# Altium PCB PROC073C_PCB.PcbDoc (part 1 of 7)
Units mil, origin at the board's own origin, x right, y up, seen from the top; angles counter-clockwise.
Board outline 2165.35 x 2695.12 mil, 8 copper layers (Top Layer, L2_GND, L3_SIGNAL 1, L4_SIGNAL 2, L5_SIGNAL 3, L6_SIGNAL 4, L7_GND, Bottom Layer), stack 55.9 mil thick; 393 components, 319 nets, 1311 pads, 1643 vias.
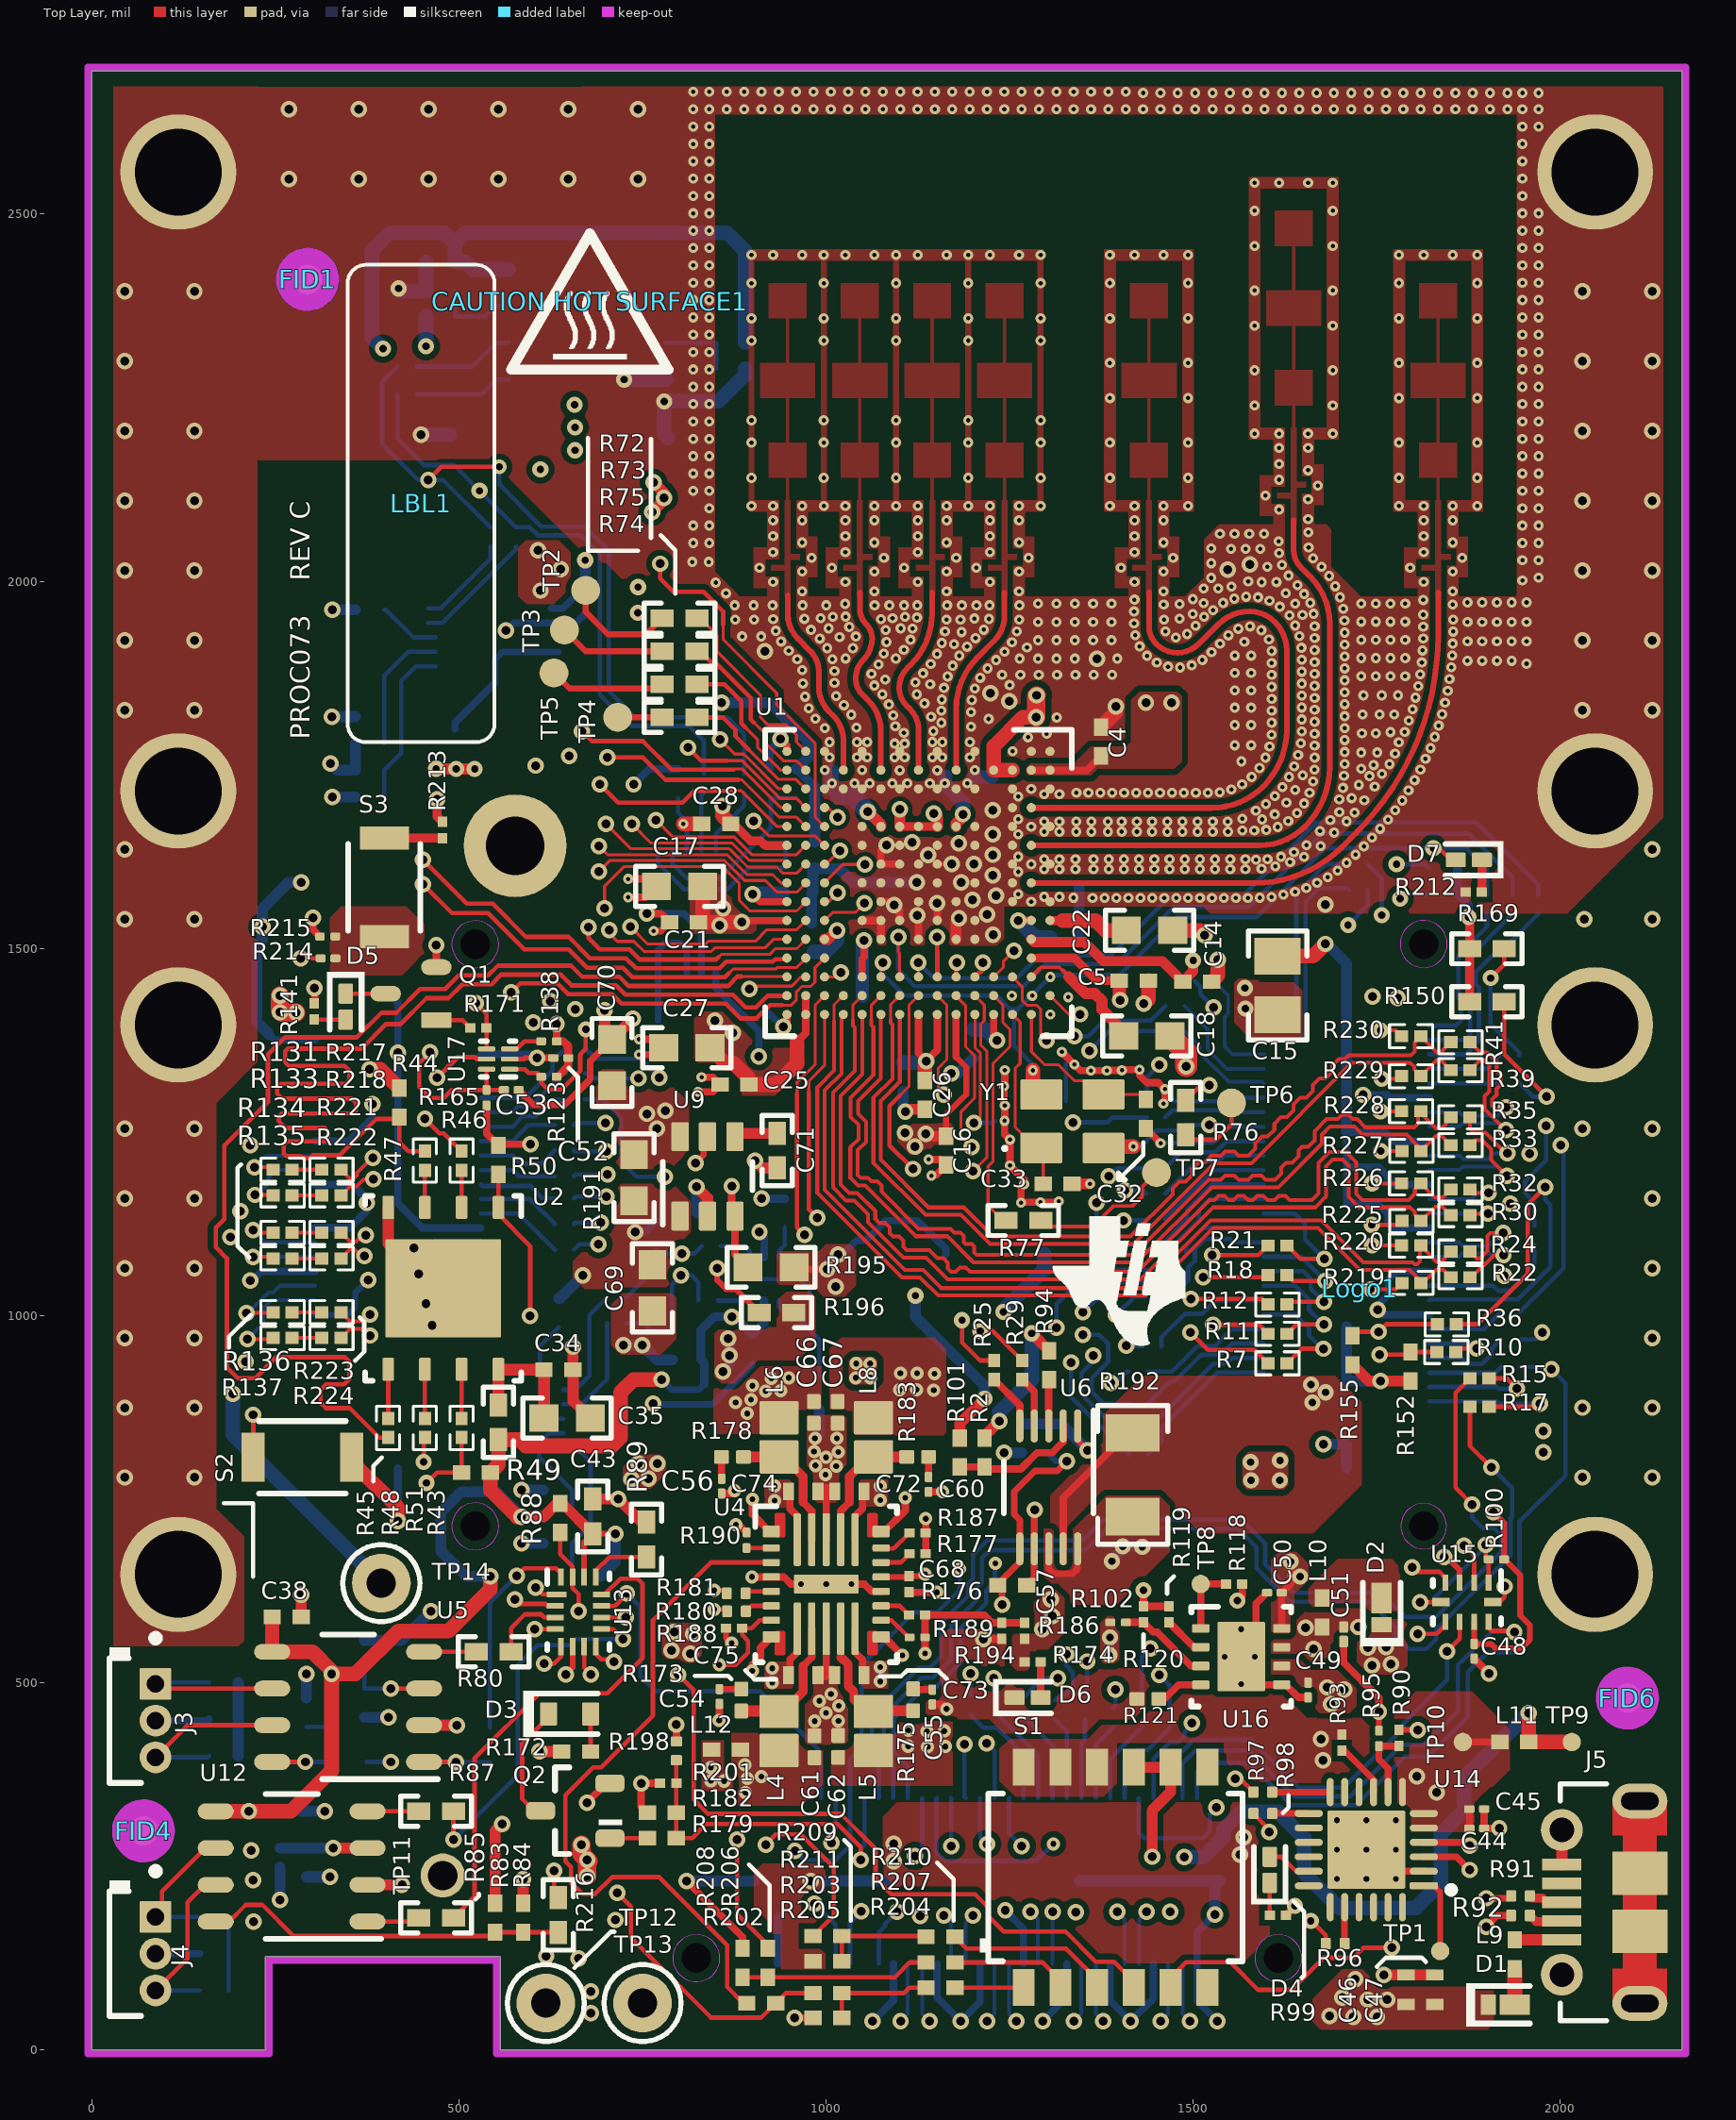
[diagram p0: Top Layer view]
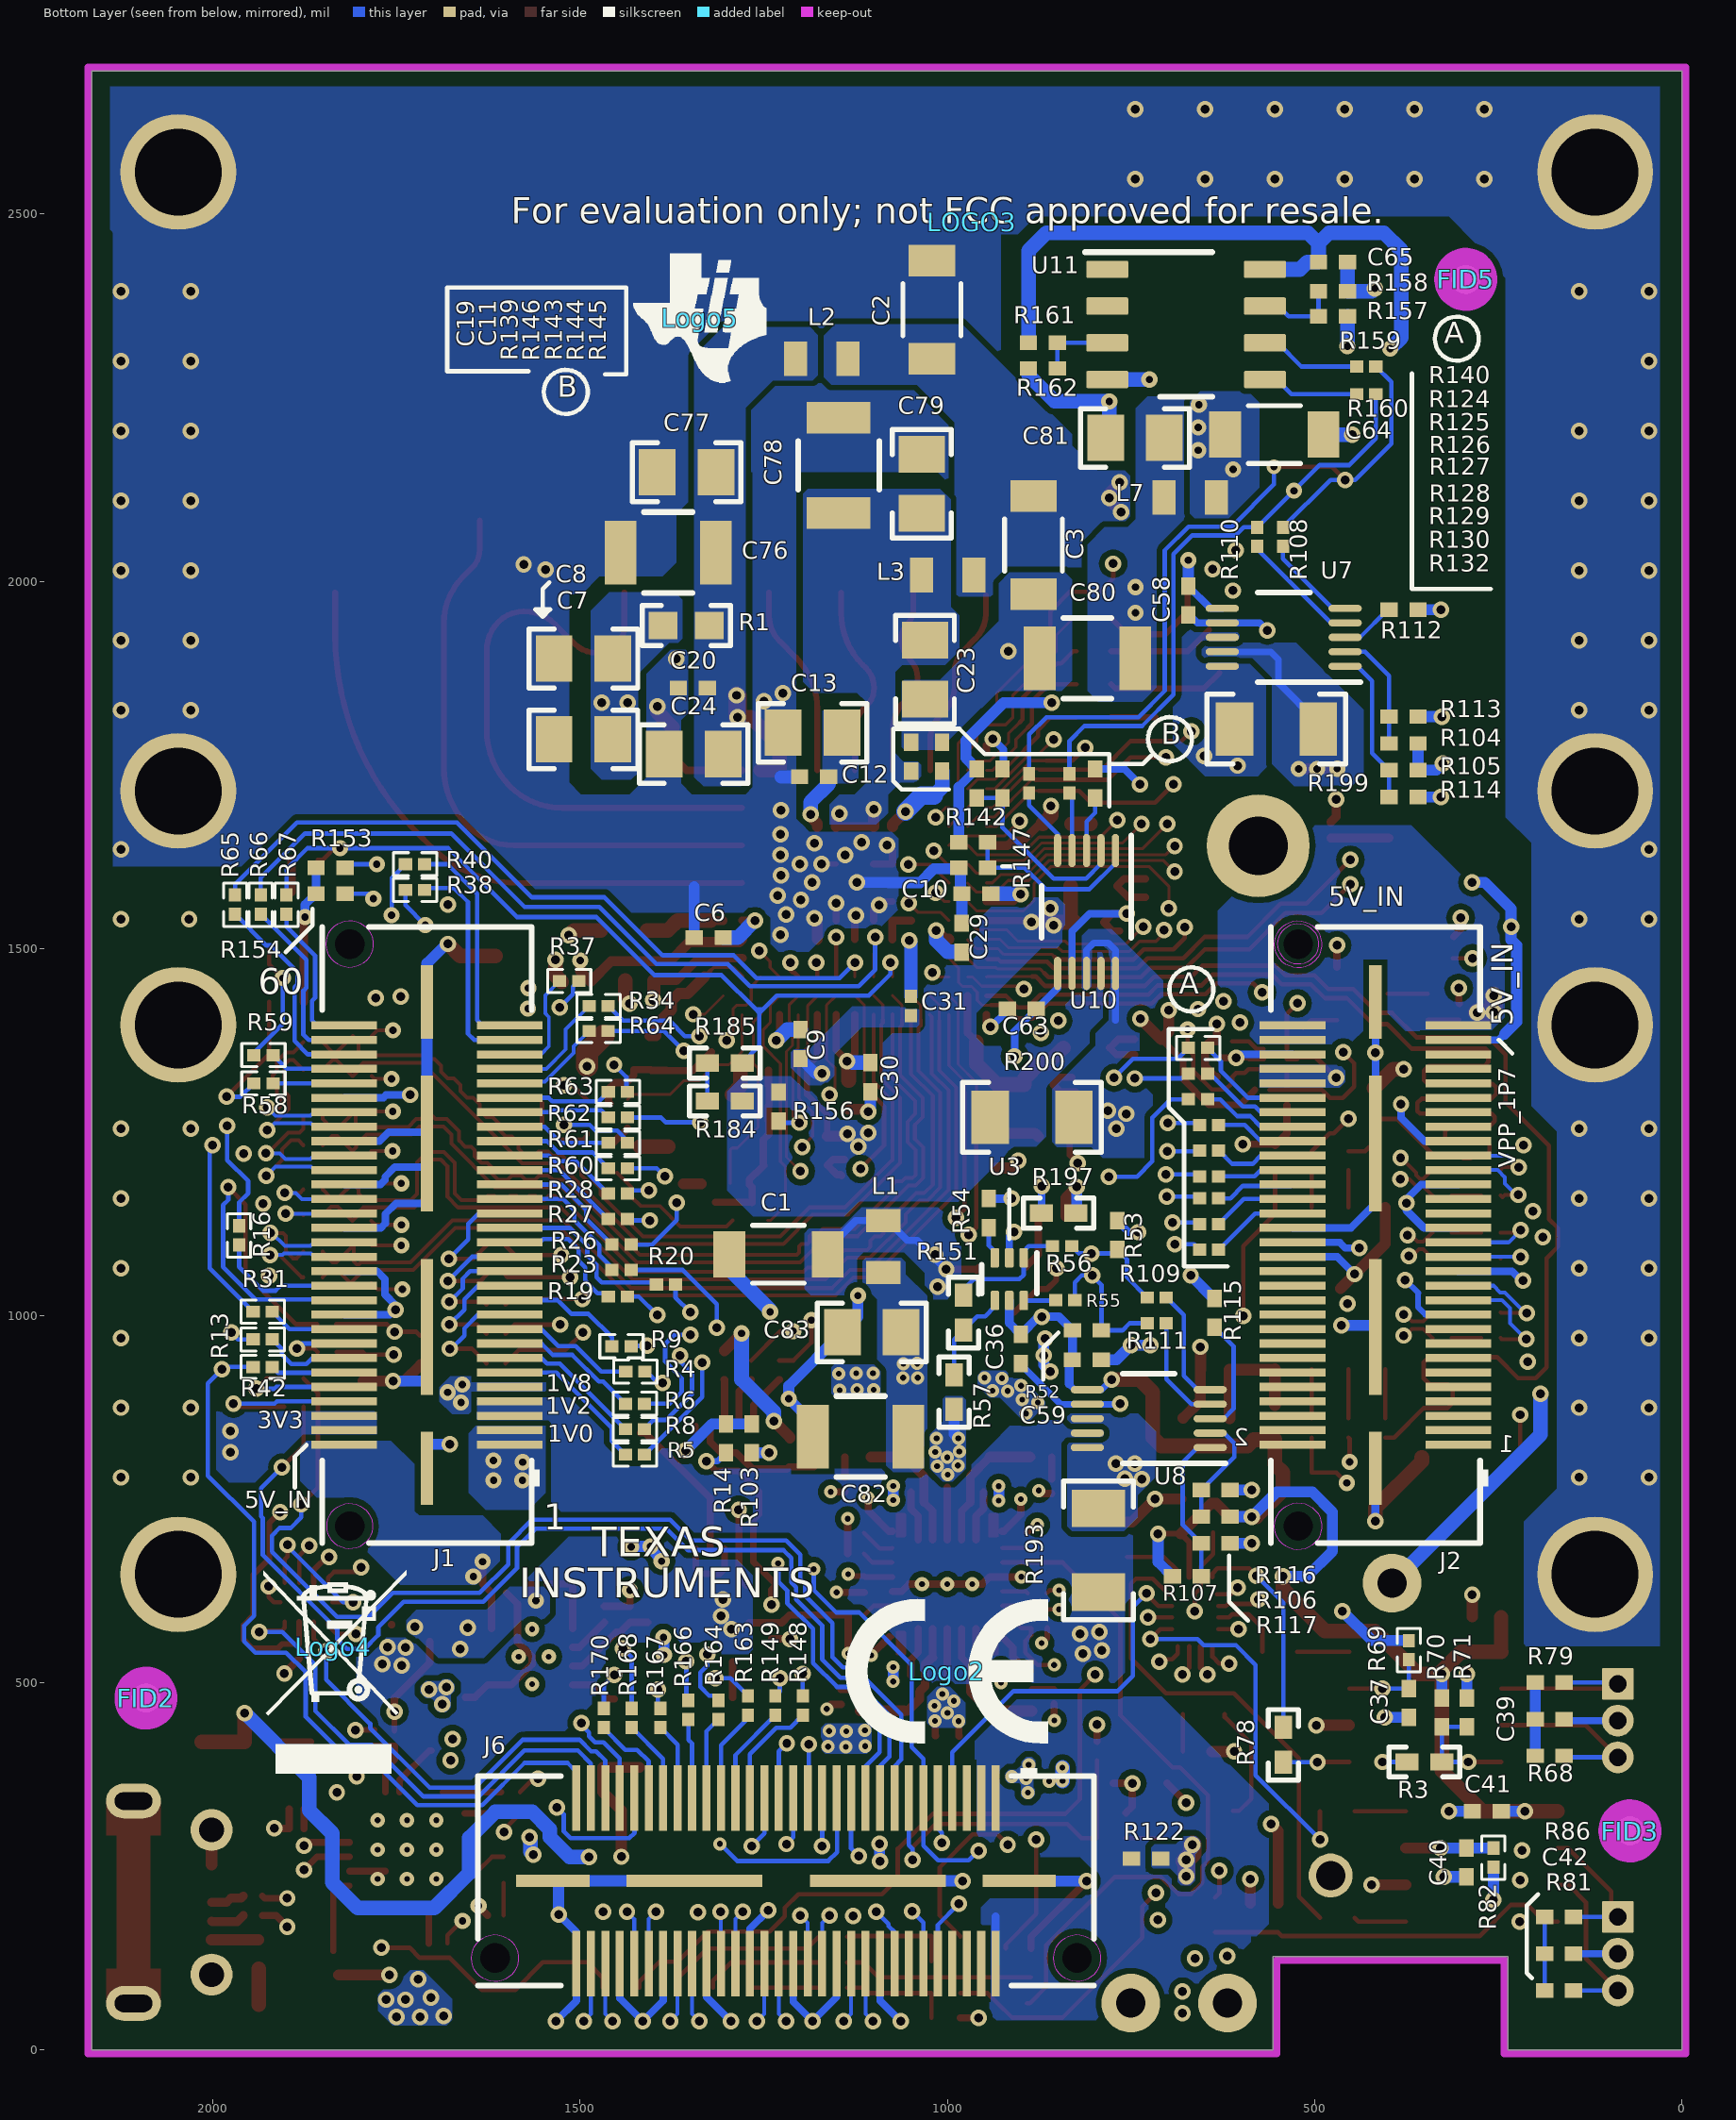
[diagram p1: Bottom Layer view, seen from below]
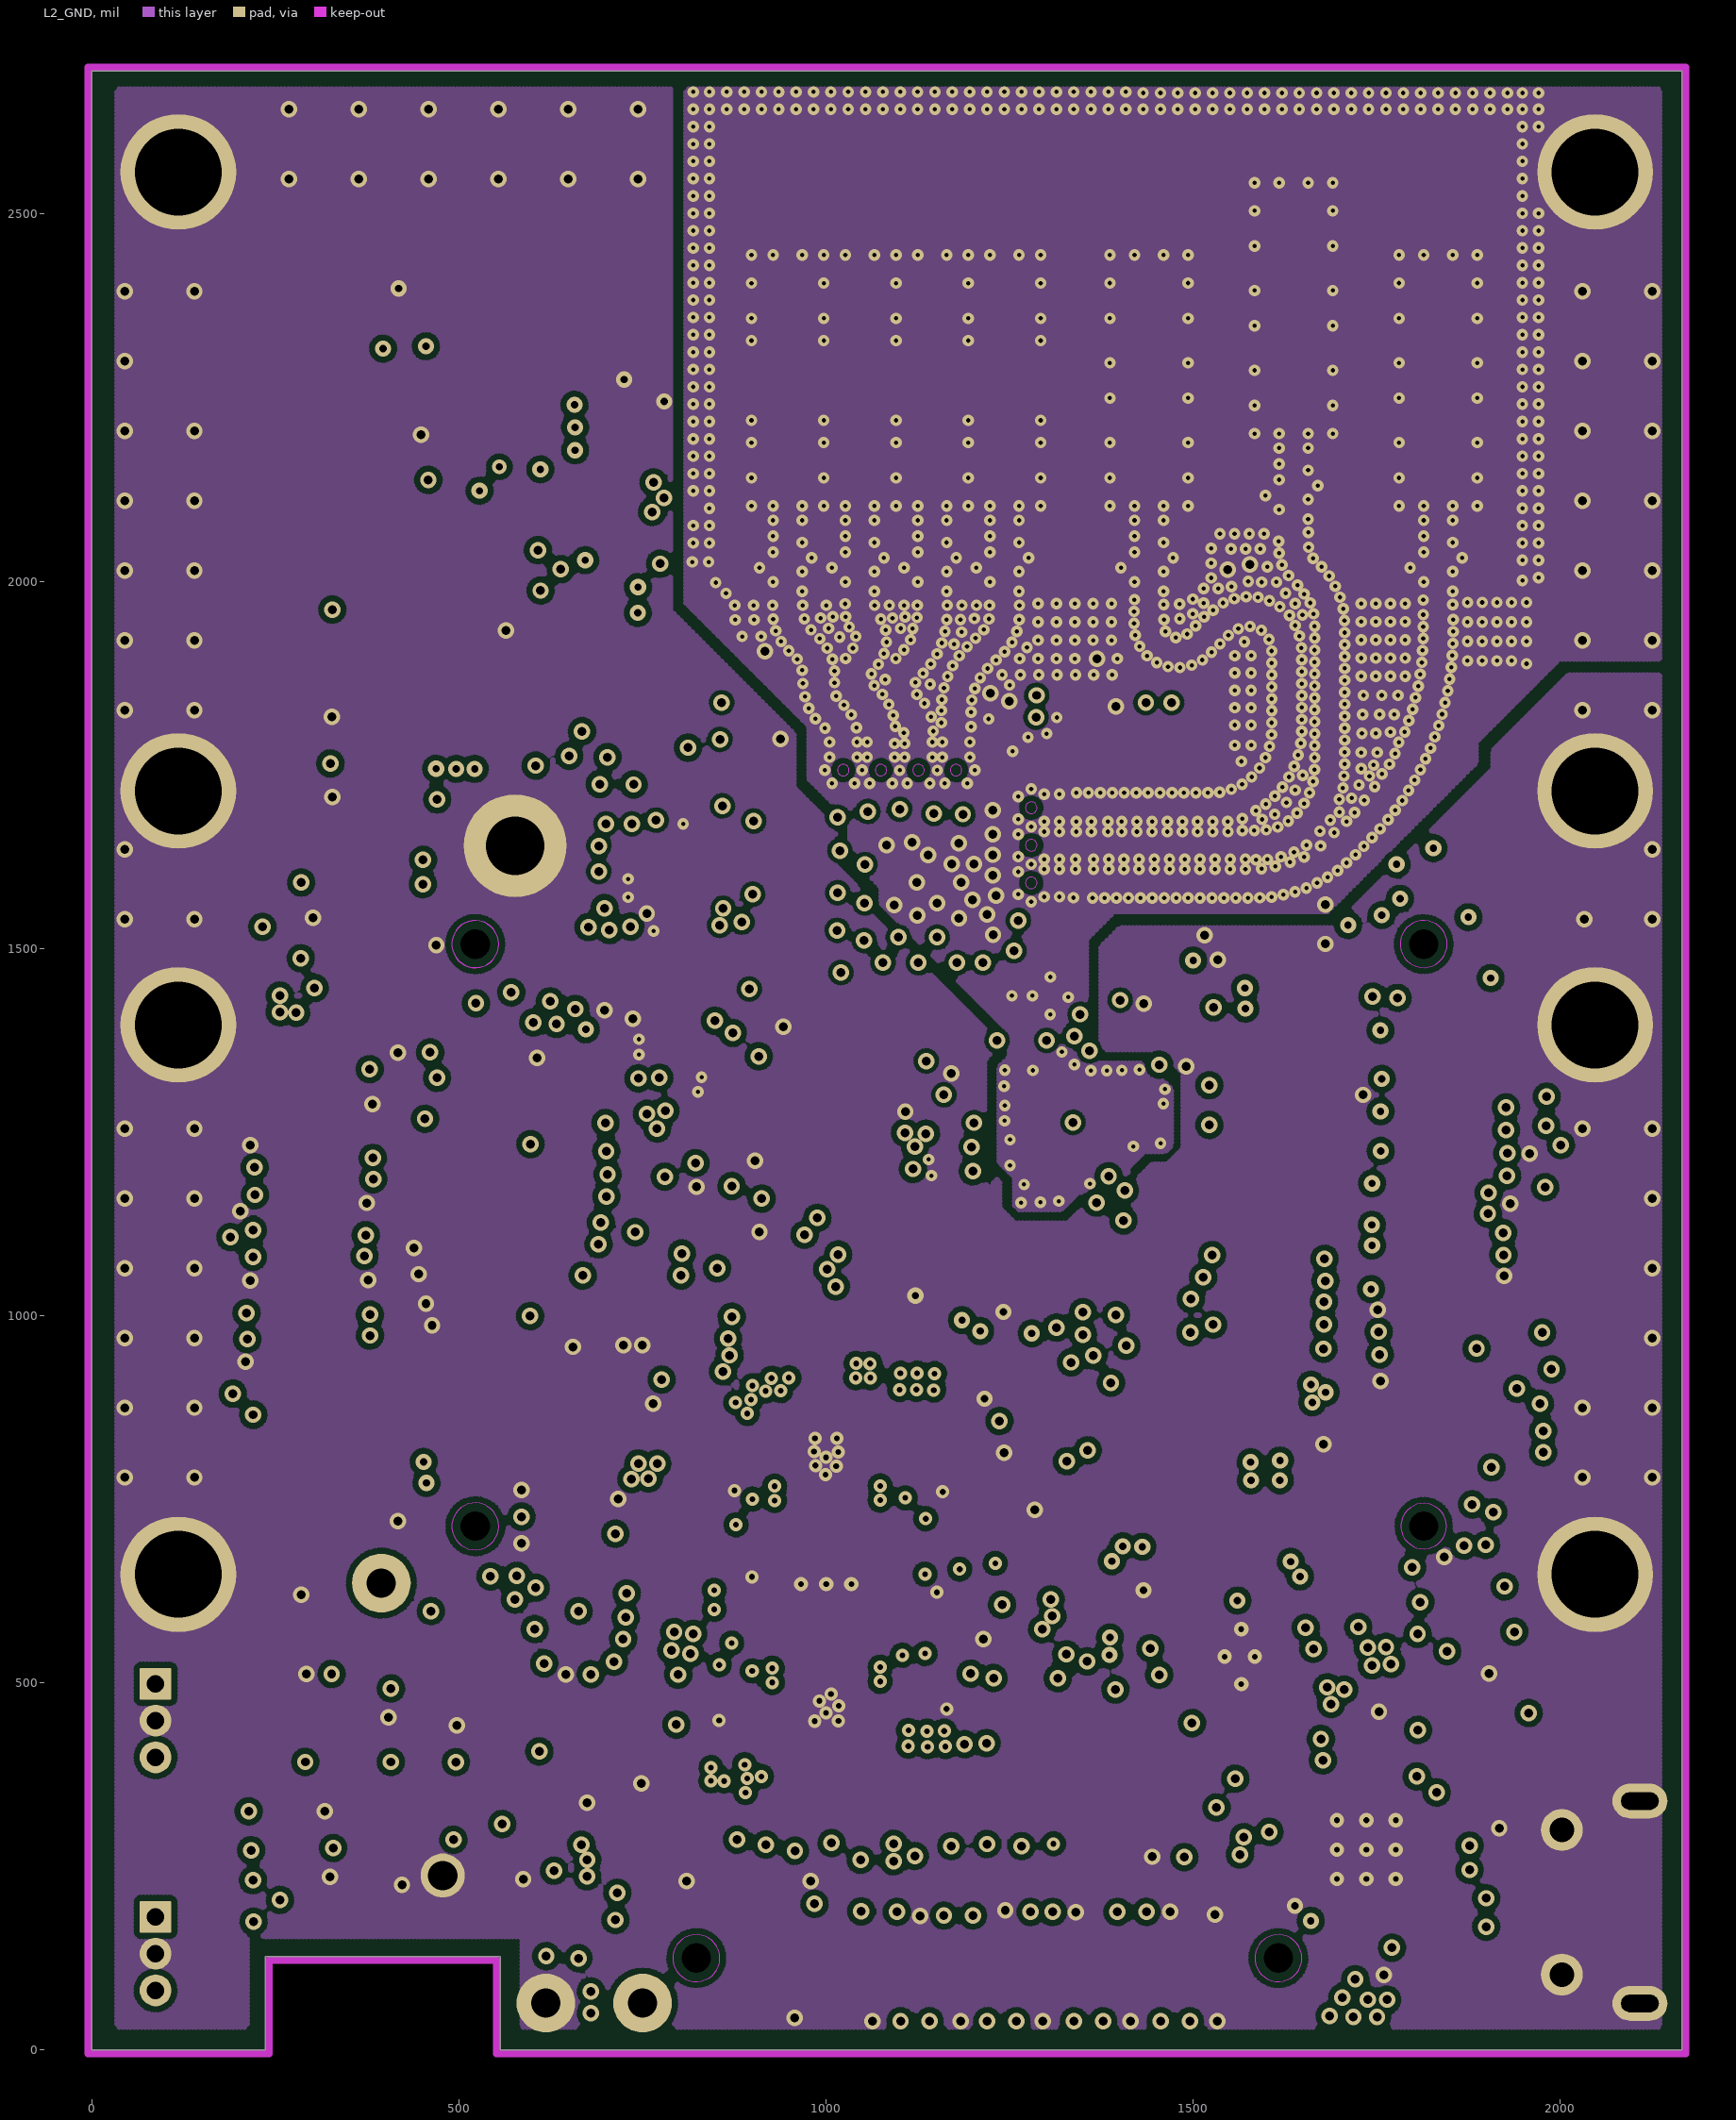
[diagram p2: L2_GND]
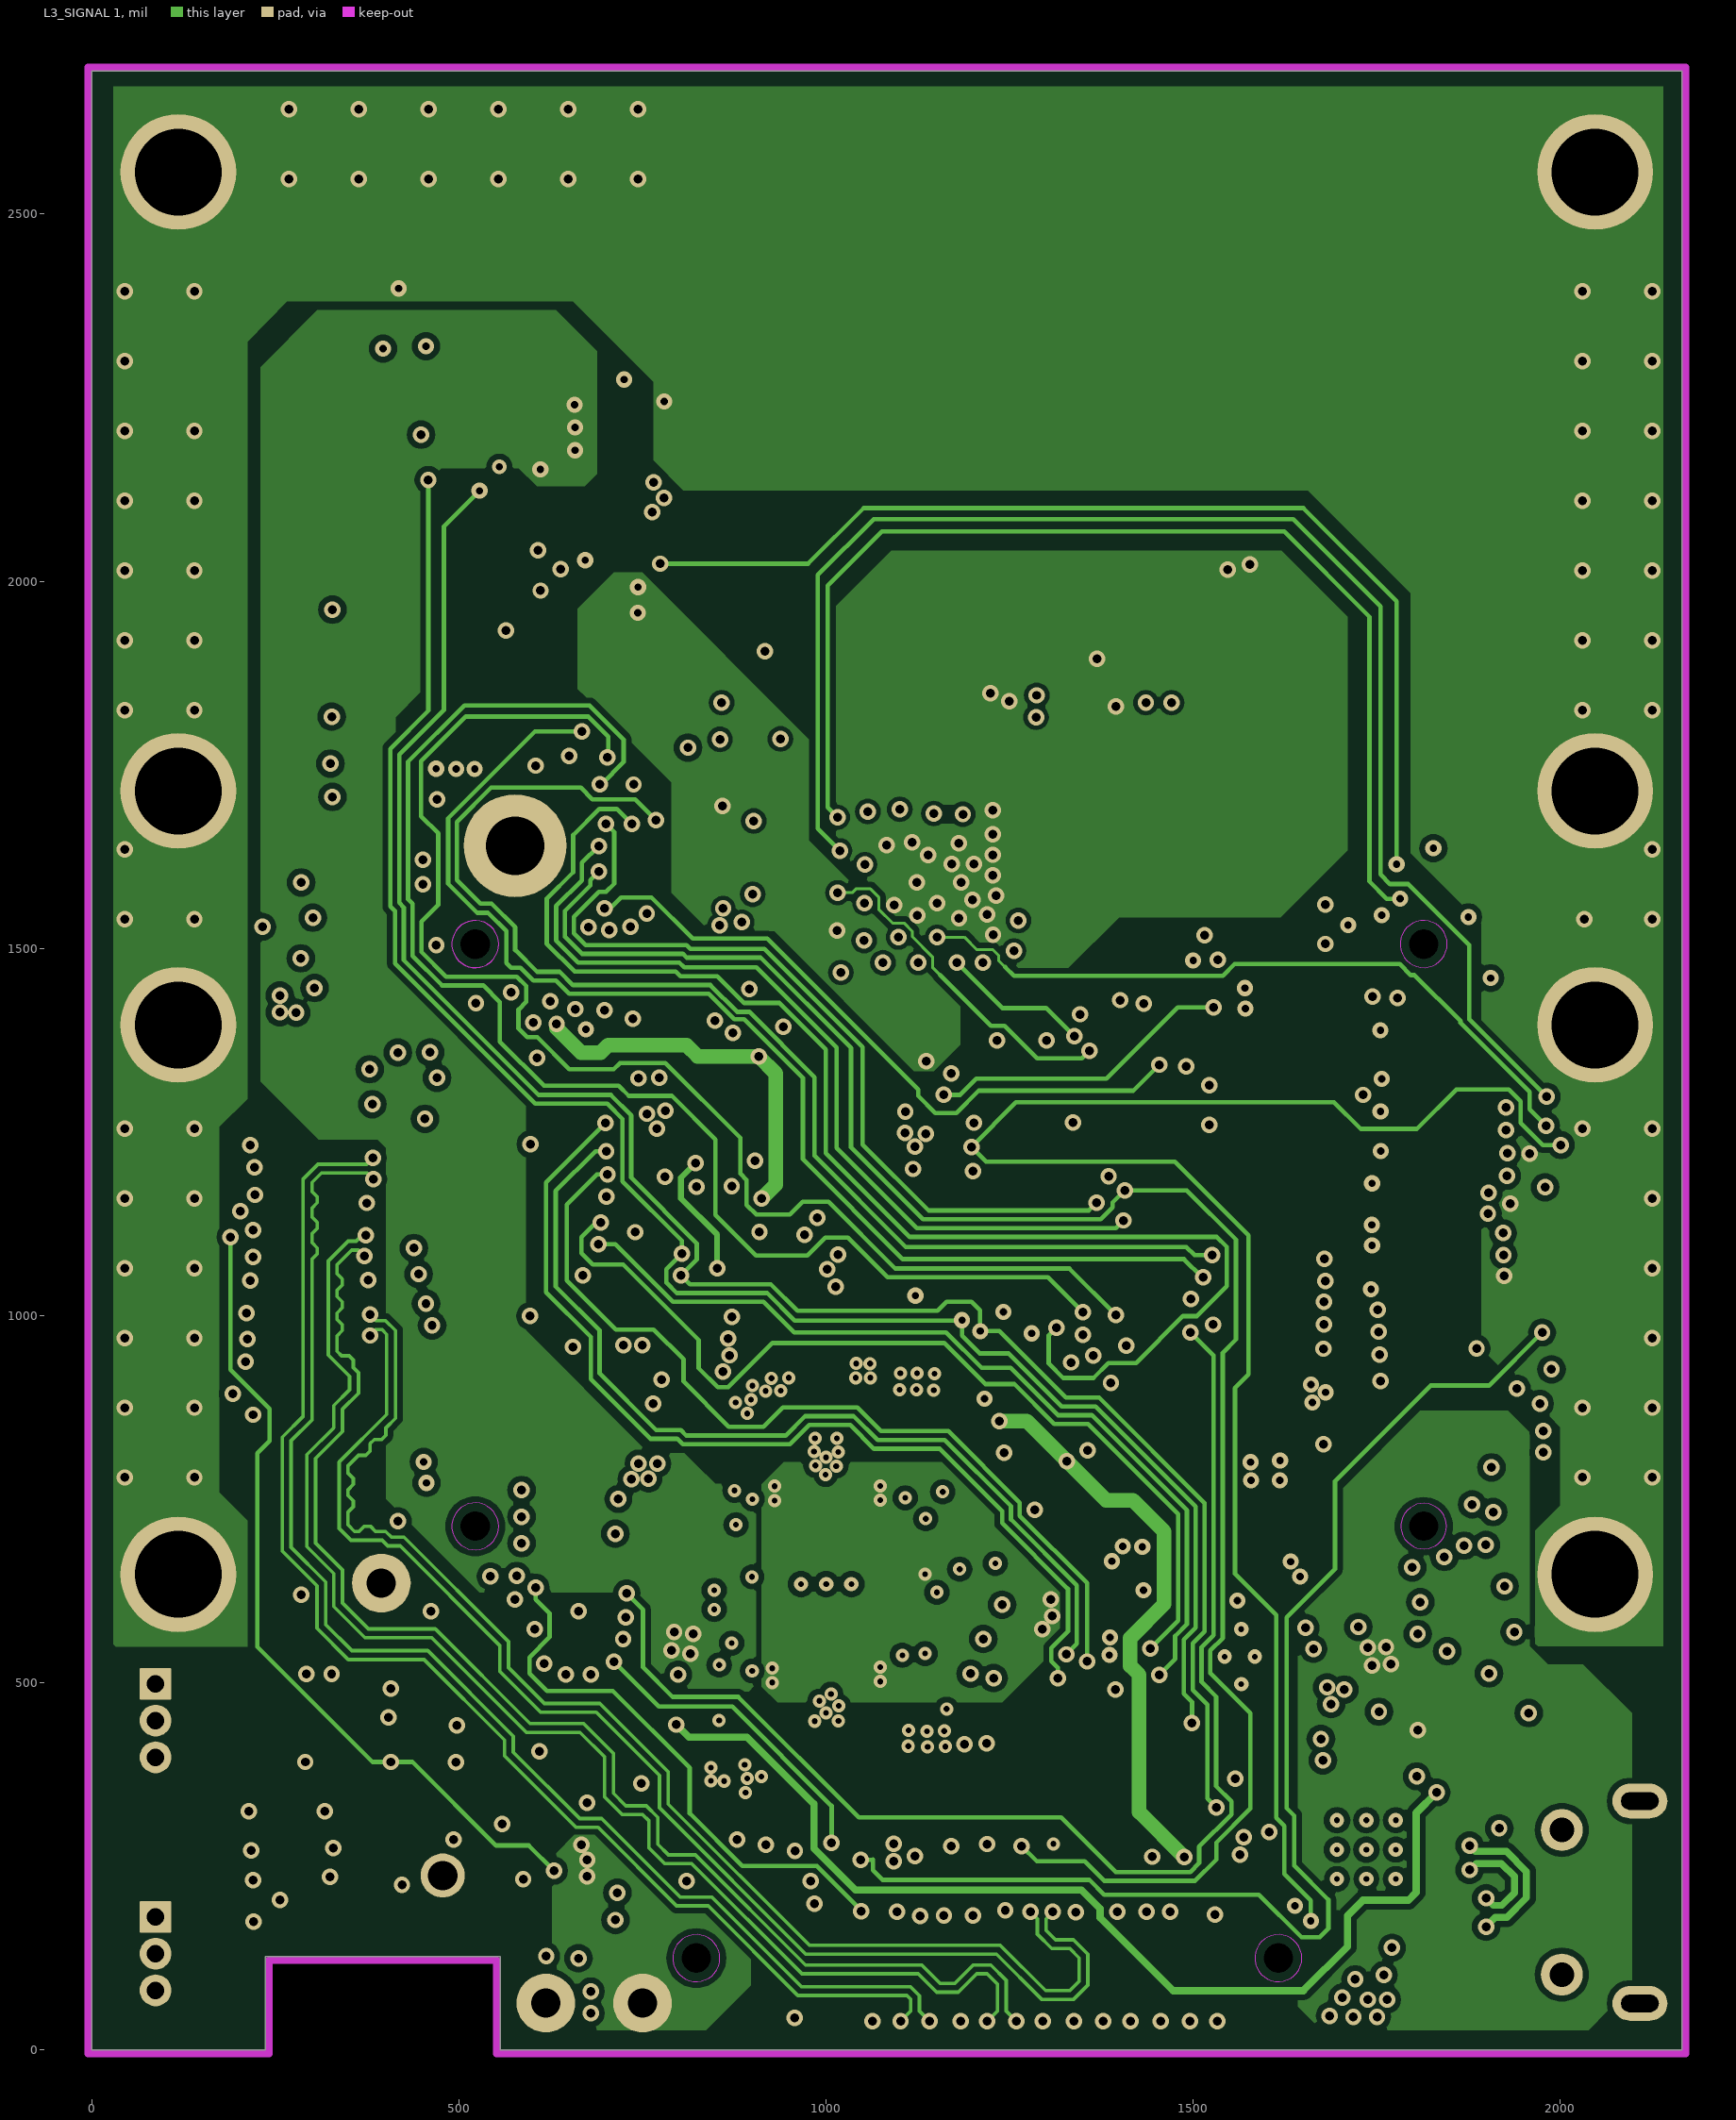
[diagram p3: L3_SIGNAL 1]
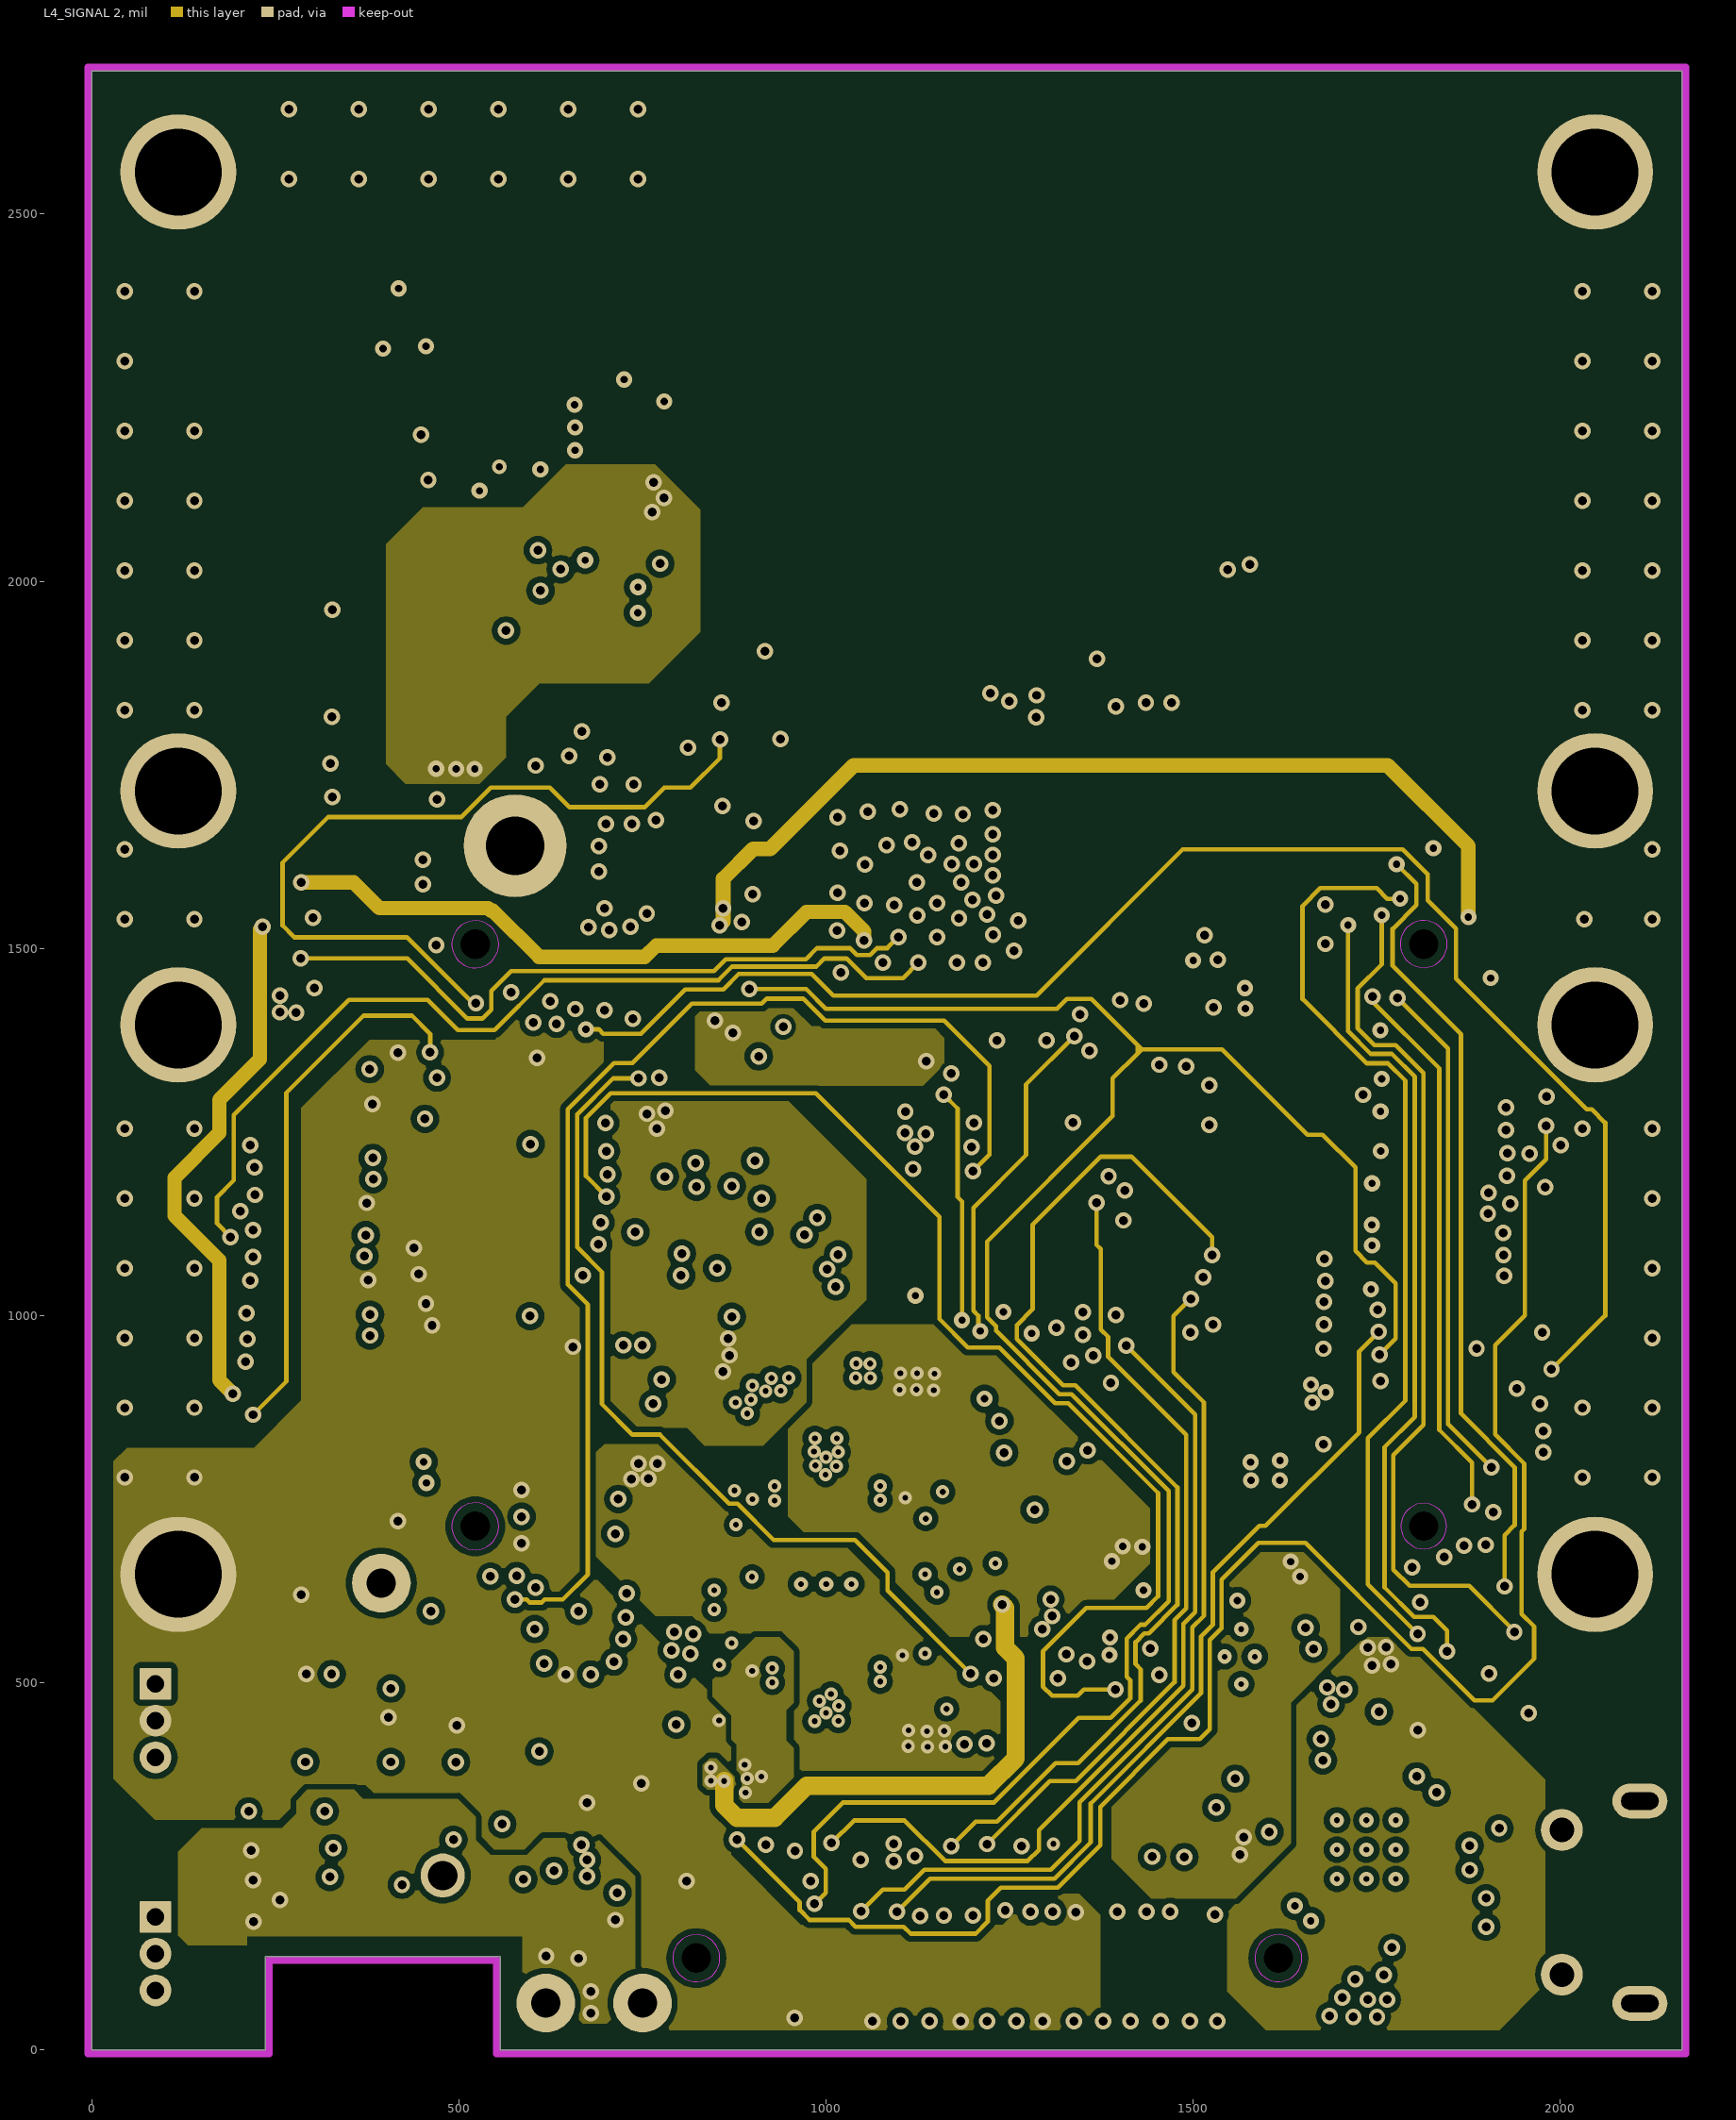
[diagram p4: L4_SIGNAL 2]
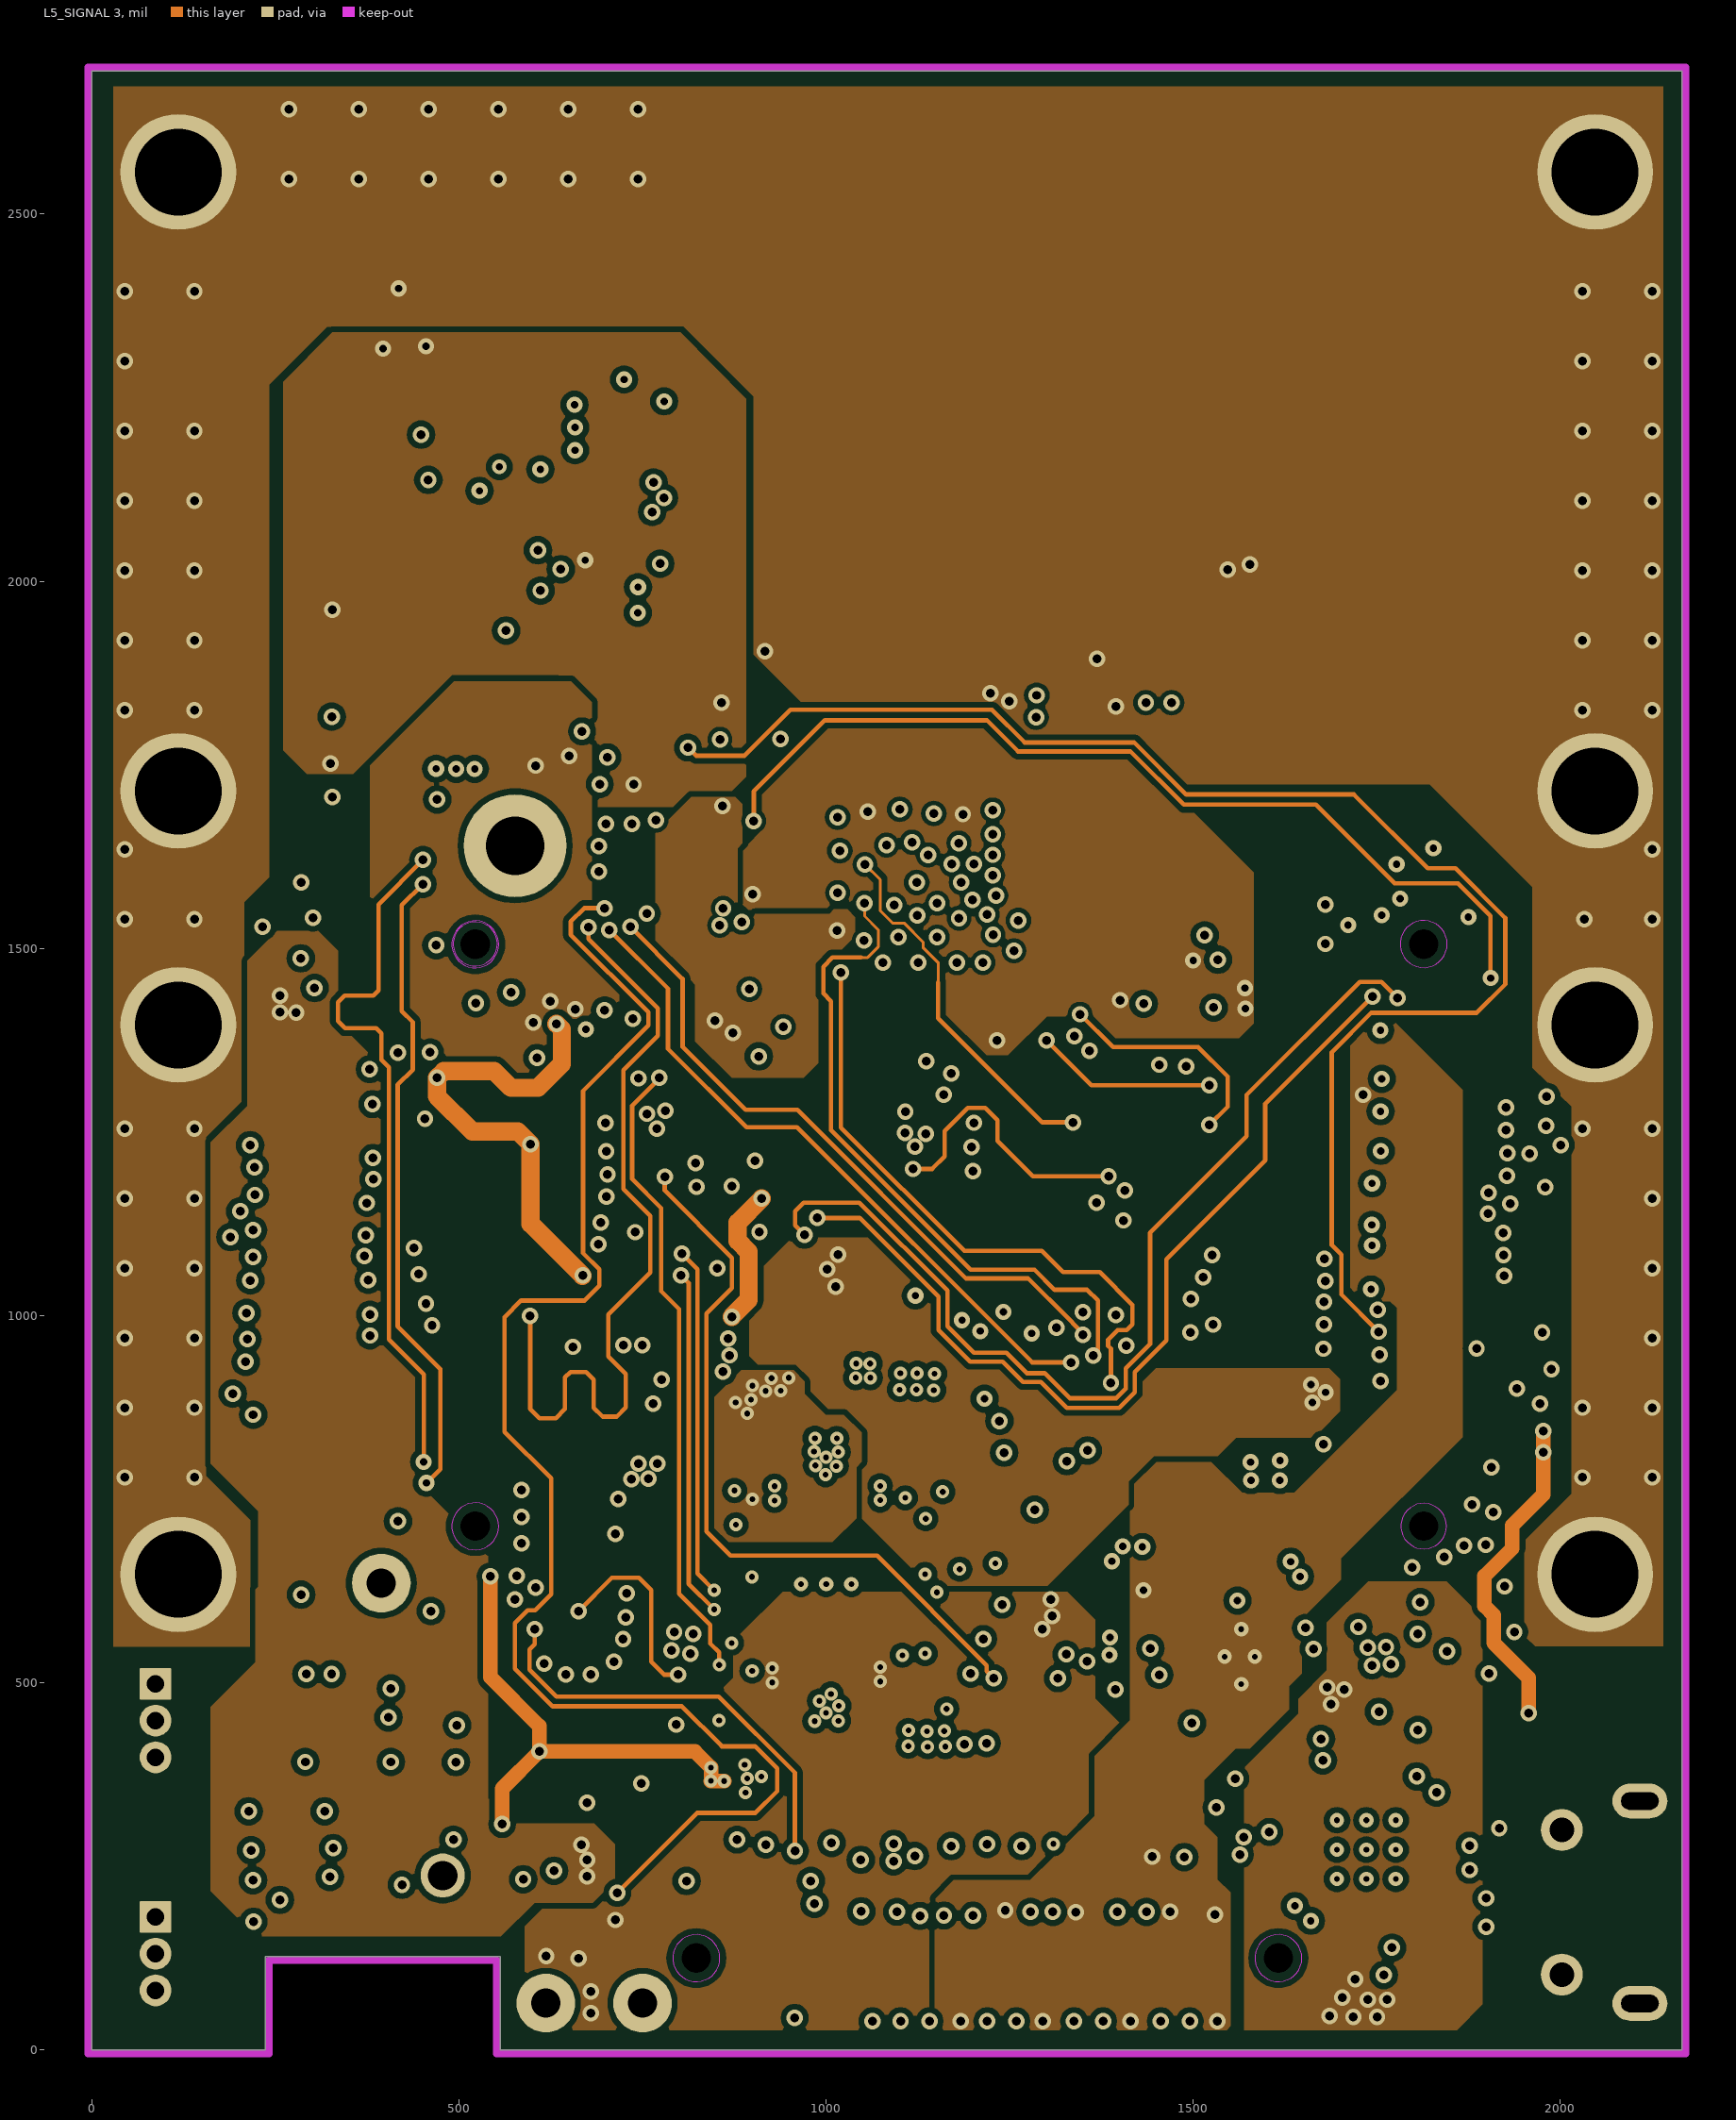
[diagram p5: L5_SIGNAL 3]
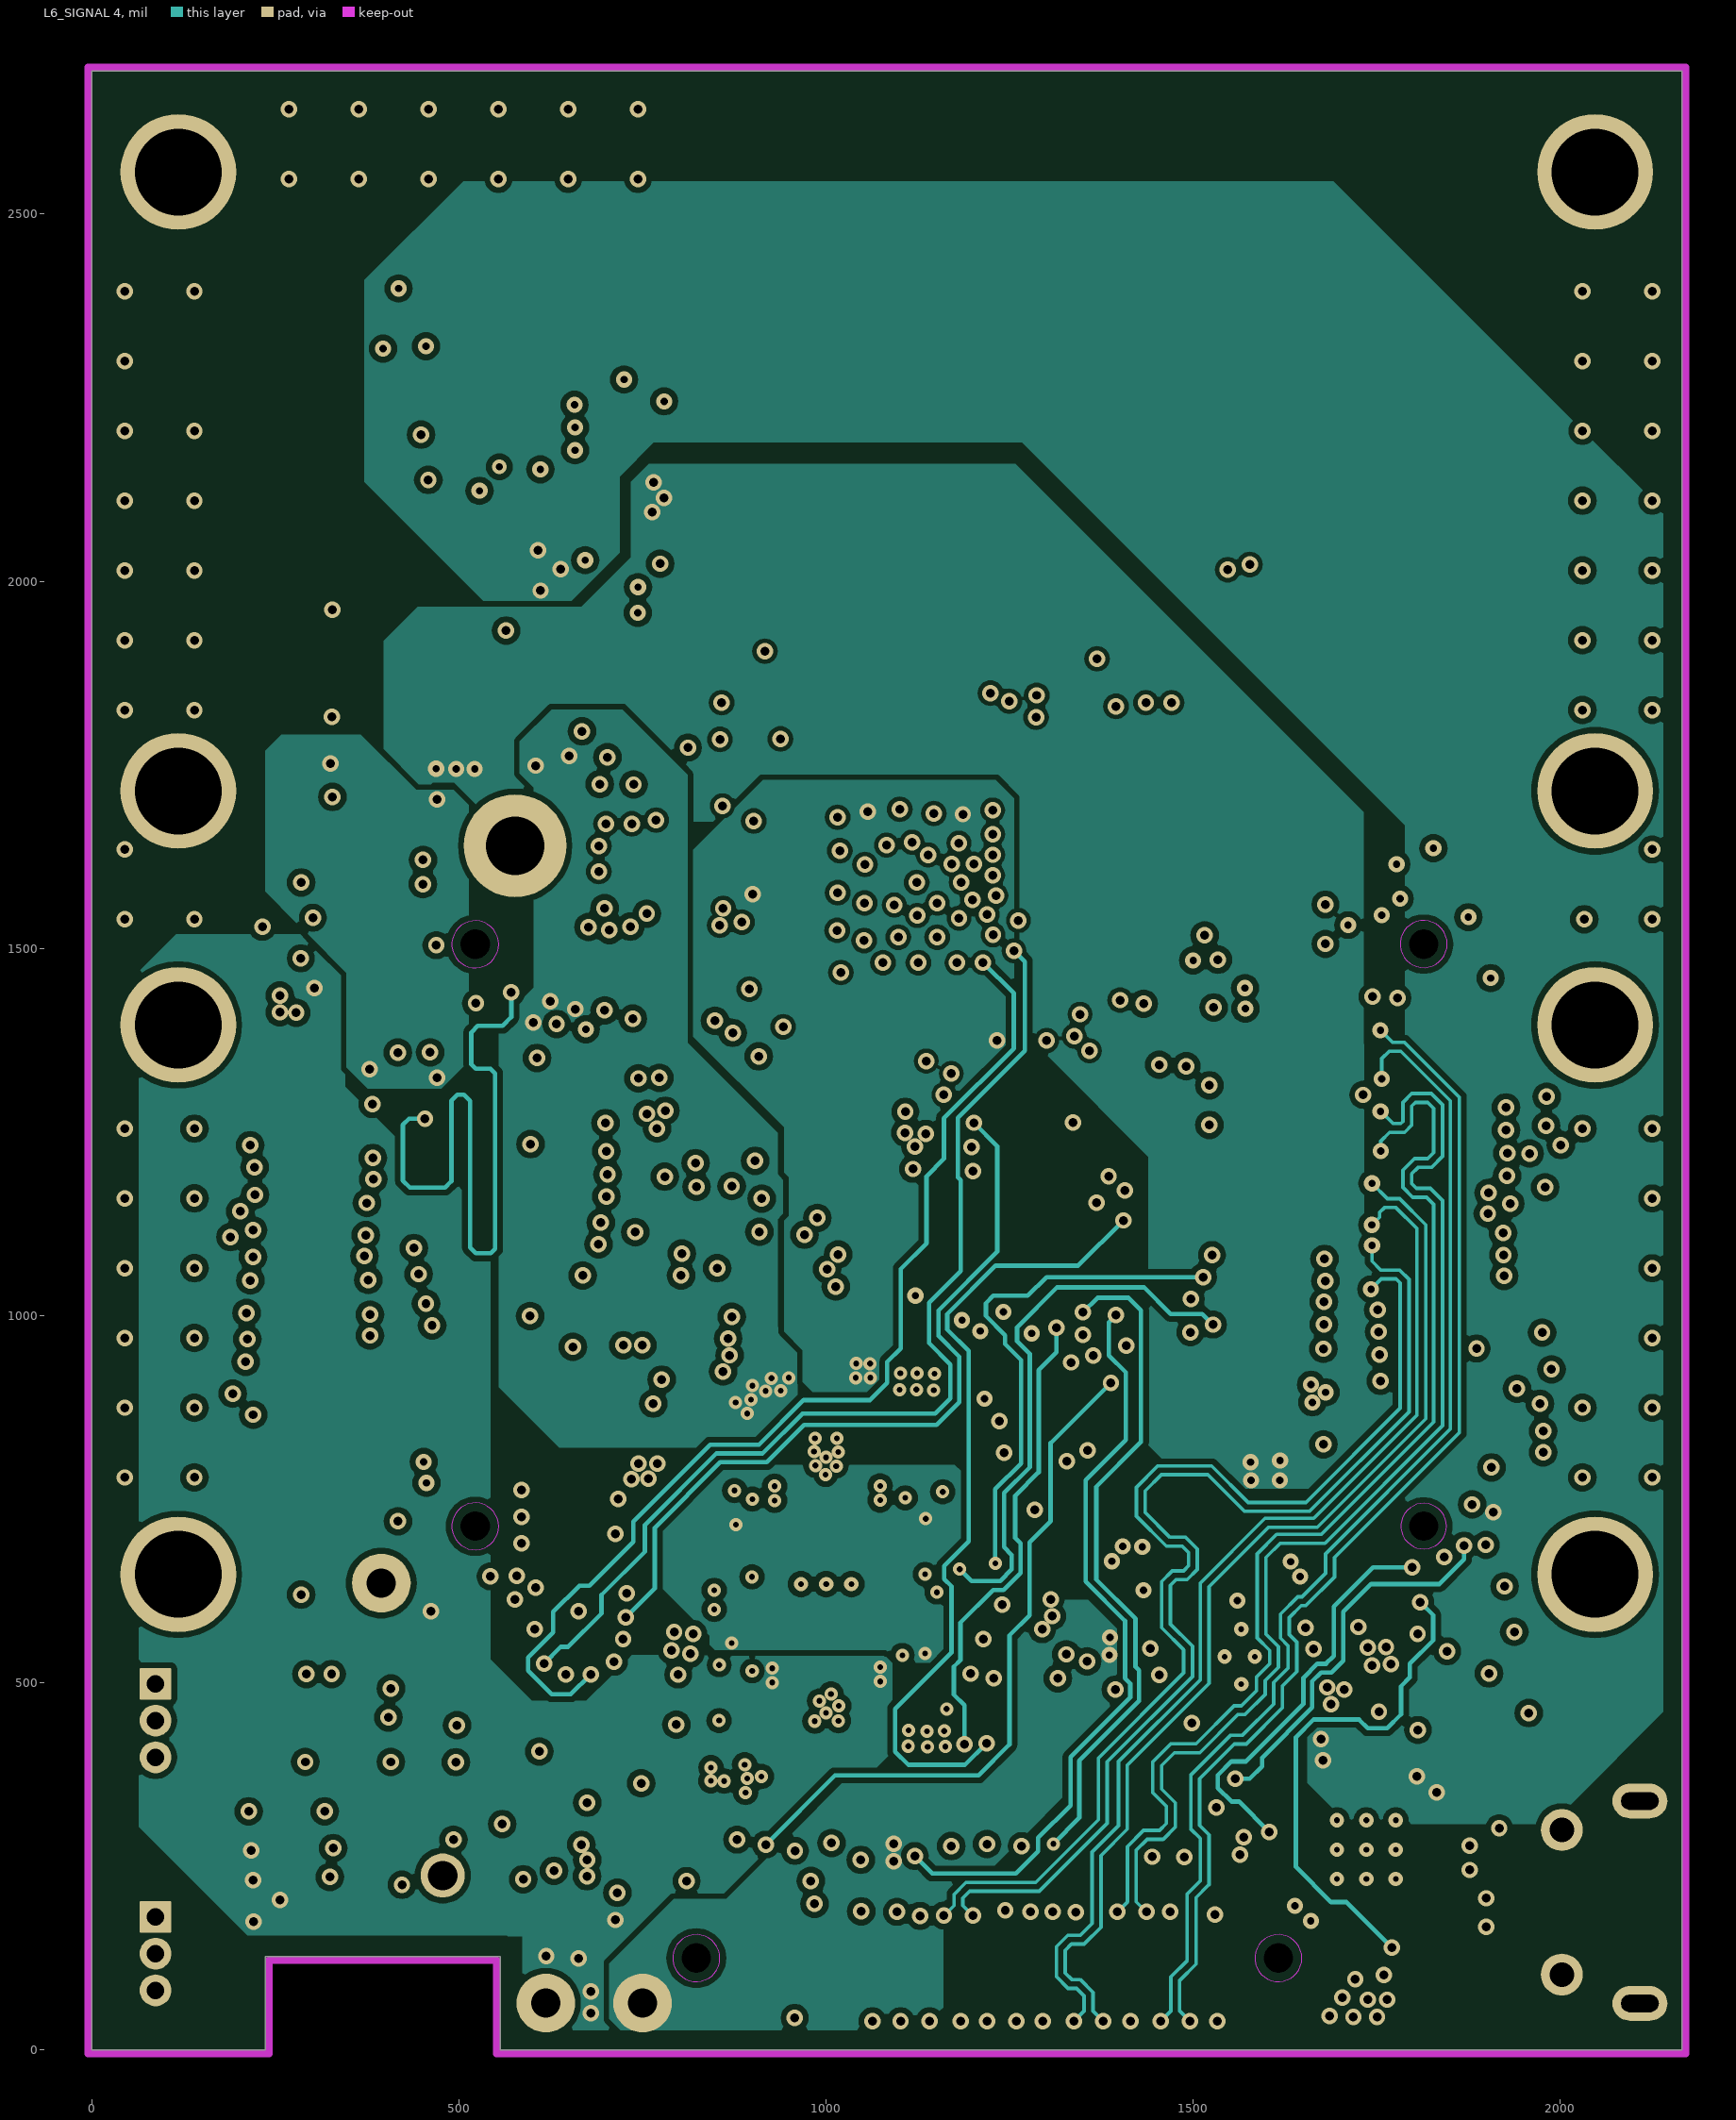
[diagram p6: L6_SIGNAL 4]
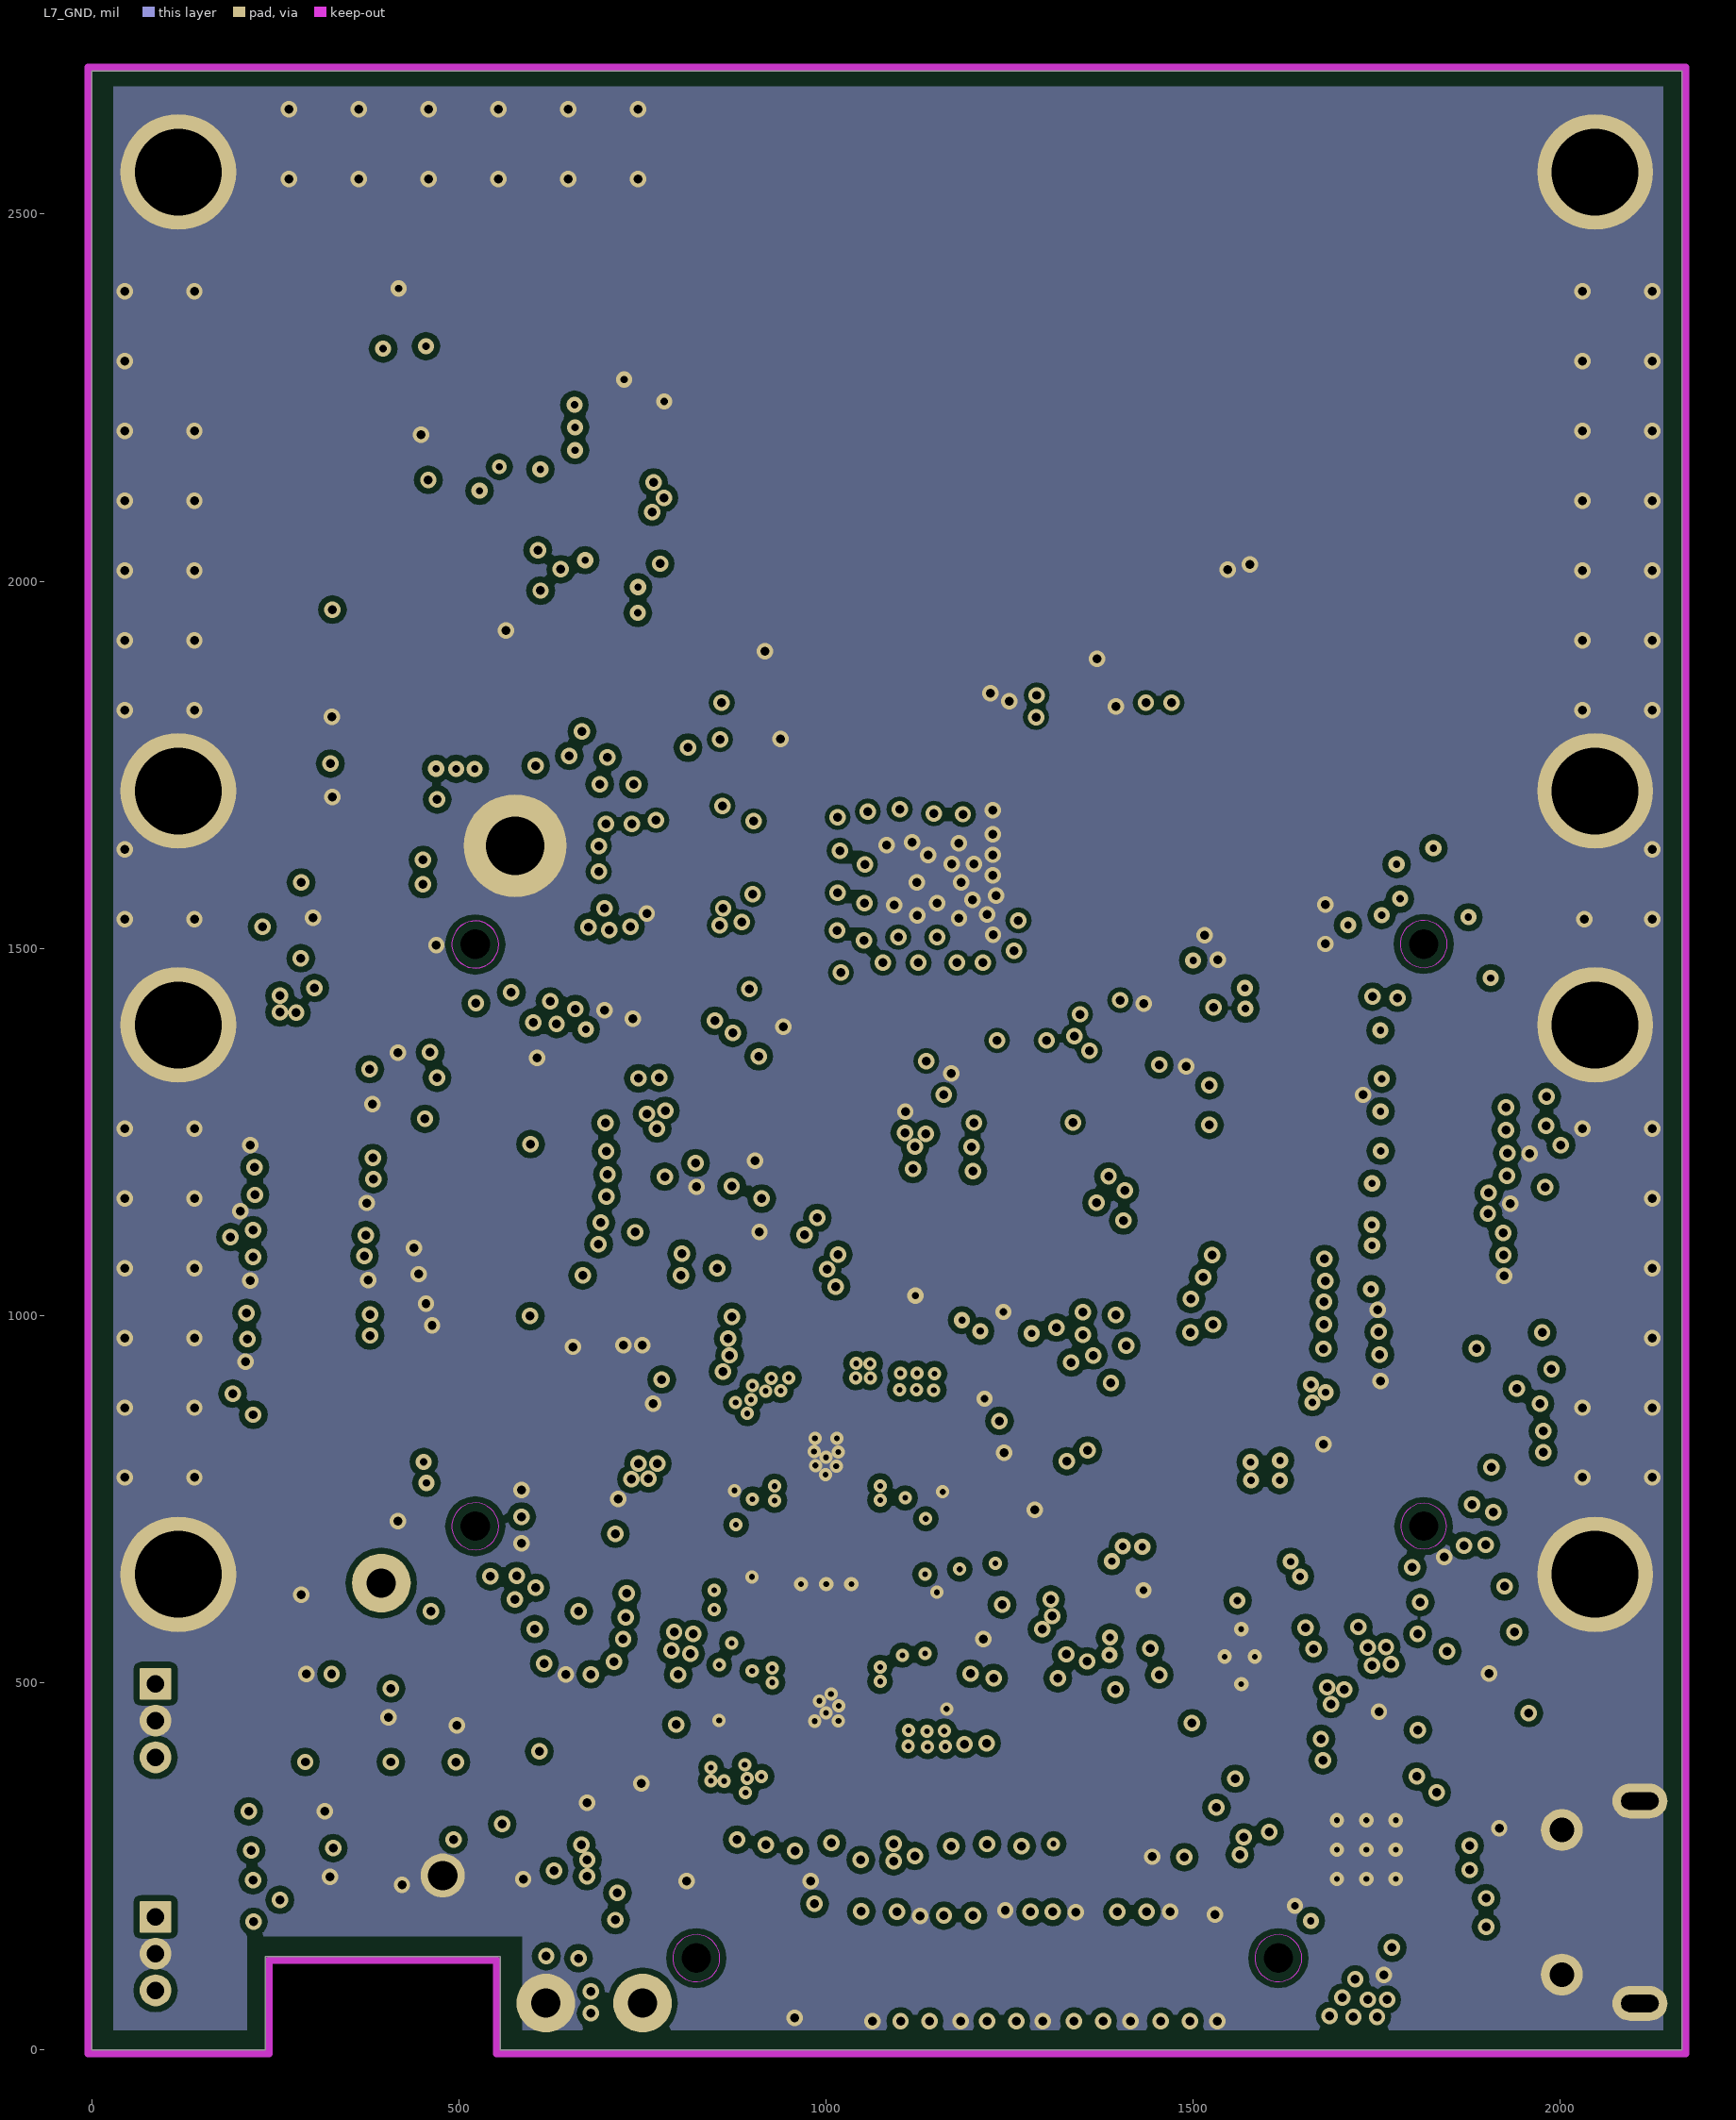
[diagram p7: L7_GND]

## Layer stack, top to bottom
Top Solder: solder mask 0.8, Solder Resist, Dk 1
Top Layer: signal copper 1.6
Dielectric 1: core 3.9, RO4835 LOPRO, Dk 3.5
L2_GND: signal copper 1.4
Dielectric 2: prepreg 5.5, PCL370HR, Dk 4.17
L3_SIGNAL 1: signal copper 1.4
Dielectric 3: core 10, PCL370HR, Dk 4.17
L4_SIGNAL 2: signal copper 1.4
Dielectric 4: prepreg 5.5, PCL370HR, Dk 4.17
L5_SIGNAL 3: signal copper 1.4
Dielectric 5: prepreg 10, PCL370HR, Dk 4.17
L6_SIGNAL 4: signal copper 1.4
Dielectric 6: core 5.5, PCL370HR, Dk 4.17
L7_GND: signal copper 1.4
Dielectric 7: core 3.9, PCL370HR, Dk 4.17
Bottom Layer: signal copper 1.6
Bottom Solder: solder mask 0.8, Solder Resist, Dk 1

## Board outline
0,0 0,2695.12 2165.35,2695.12 2165.35,0 556.54,0 556.54,127.3 236.54,127.3 236.54,0

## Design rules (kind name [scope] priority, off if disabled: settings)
AcuteAngle [All] p1 off: minimum=4.50000000000000E+0001 checktracksonly=FALSE
AssemblyTestPointUsage [All] p1: valid=2
Clearance Clearance_KO-J5 [IsKeepOut and IsTrack vs InComponent('J5')] p1: gap=19.6 ignorepadtopadclearanceinfootprint=TRUE
Clearance Clearance_Keepout [IsKeepOut and IsTrack] p2: gap=20 ignorepadtopadclearanceinfootprint=TRUE
Clearance Clearance_LVDS_Track [istrack and InNetClass('LVDS') vs istrack and InNetClass('LVDS')] p3: gap=5 ignorepadtopadclearanceinfootprint=FALSE
Clearance Clearance_LVDS [InNetClass('LVDS') and IsTrack vs (isvia or IsThruPin) and (not InNetClass('LVDS') or not InNet('GND'))] p4: gap=8 ignorepadtopadclearanceinfootprint=FALSE
Clearance Clearance_Region [isregion and incomponent('U4') vs IsTrack] p5: gap=5 ignorepadtopadclearanceinfootprint=FALSE
Clearance "Clr_L2_GND Cut out (400 Mircrons)" [OnLayer('L2') and InPolygon vs IsKeepOut] p6: gap=0 ignorepadtopadclearanceinfootprint=FALSE except(7: Arc-Arc Arc-Track)
Clearance "Clr_L1_GND Cut Out (800 Mirons)_1" [OnLayer('L2')] p7: gap=6 ignorepadtopadclearanceinfootprint=FALSE except(0: Arc-Hole Track-Hole SMDPad-Hole THPad-Hole Via-Hole Fill-Hole Poly-Hole Region-Hole Text-Hole; 8: Arc-Fill Arc-Poly Arc-Region Track-Fill Track-Poly Track-Region SMDPad-Fill SMDPad-Poly SMDPad-Region THPad-Fill THPad-Poly THPad-Region Via-Fill Via-Poly Via-Region Fill-Fill Fill-Poly Fill-Region Poly-Poly Poly-Region Region-Region)
Clearance Clearance_Fid [IsKeepOut and InComponentClass('FiducialMark') vs IsPad and InComponentClass('FiducialMark')] p8: gap=0 ignorepadtopadclearanceinfootprint=FALSE
Clearance "Clearance_Diff Pairs_LVDS" [InNetClass('Diff Pairs') vs InNetClass('Diff Pairs')] p9: gap=6 ignorepadtopadclearanceinfootprint=FALSE except(0: Arc-Hole Track-Hole SMDPad-Hole THPad-Hole Via-Hole Fill-Hole Poly-Hole Region-Hole Text-Hole; 4: Arc-SMDPad Arc-THPad Arc-Via Track-SMDPad Track-THPad Track-Via; 5: Arc-Arc Arc-Track Track-Track; 8: Arc-Fill Arc-Poly Arc-Region Track-Fill Track-Poly Track-Region Via-Fill Via-Poly Via-Region Fill-Fill Fill-Poly Fill-Region Poly-Poly Poly-Region Region-Region)
Clearance "Clr_L1_GND Cut Out (800 Mirons)" [OnTopLayer and InPoly vs IsKeepOut] p10: gap=0 ignorepadtopadclearanceinfootprint=FALSE
Clearance "Clearance_TX and RX" [InNetClass('TX and RX')] p11: gap=8 ignorepadtopadclearanceinfootprint=FALSE except(0: Arc-Hole Track-Hole SMDPad-Hole THPad-Hole Via-Hole Fill-Hole Poly-Hole Region-Hole Text-Hole; 4: Arc-Text Track-Text SMDPad-Text THPad-Text Via-Text Fill-Text Poly-Text Region-Text Text-Text; 7.7: Fill-Fill Fill-Poly Fill-Region Poly-Poly Poly-Region Region-Region; 7.9: Arc-Via Track-Via; 10: Arc-SMDPad Arc-THPad Track-SMDPad Track-THPad SMDPad-SMDPad SMDPad-THPad SMDPad-Via THPad-THPad THPad-Via)
Clearance Clearance_BGA [WithinRoom('BGA1')] p12: gap=4 ignorepadtopadclearanceinfootprint=FALSE except(0: Arc-Hole Track-Hole SMDPad-Hole THPad-Hole Via-Hole Fill-Hole Poly-Hole Region-Hole Text-Hole; 6: SMDPad-Poly THPad-Poly Via-Poly; 7.5: Region-Region; 7.87: Arc-Text Track-Text SMDPad-Text THPad-Text Via-Text Fill-Text Poly-Text Region-Text Text-Text; 8: Arc-Poly Track-THPad Track-Poly THPad-THPad Fill-Poly Poly-Poly)
Clearance [All] p13: gap=8 ignorepadtopadclearanceinfootprint=TRUE except(0: Arc-Hole Track-Hole SMDPad-Hole THPad-Hole Via-Hole Fill-Hole Poly-Hole Region-Hole Text-Hole; 4: Arc-SMDPad Track-SMDPad; 5.1: SMDPad-SMDPad; 6: Arc-Arc Arc-Track Arc-THPad Arc-Via Arc-Text Track-Track Track-THPad Track-Via Track-Text SMDPad-THPad SMDPad-Via SMDPad-Text THPad-THPad THPad-Via THPad-Text Via-Via Via-Text Fill-Text Poly-Text Region-Text Text-Text)
ComponentClearance ComponentClearance_MatingCon-3D [All vs not InAnyComponent] p1: gap=0 collisioncheckmode=3 verticalgap=0 showdistances=FALSE
ComponentClearance "ComponentClearance_WEE Logo" [InComponent('Logo4')] p2: gap=0 collisioncheckmode=3 verticalgap=0 showdistances=TRUE
ComponentClearance ComponentClearance_R77 [InComponent('R77') vs InComponent('Logo1')] p3: gap=0 collisioncheckmode=3 verticalgap=0 showdistances=TRUE
ComponentClearance ComponentClearance_Logo [InComponentClass('Logo')] p4: gap=0 collisioncheckmode=3 verticalgap=0 showdistances=TRUE
ComponentClearance "ComponentClearance_Mounting Holes_Fiducial Marks" [InComponentClass('FiducialMark') vs InPadClass('Mounting Holes PADS')] p5: gap=50 collisioncheckmode=3 verticalgap=10 showdistances=TRUE
ComponentClearance [All] p6: gap=10 collisioncheckmode=3 verticalgap=10 showdistances=TRUE
DiffPairsRouting DiffPairsRouting_BGA [WithinRoom('BGA1')] p1: maxlimit=10 minlimit=10 mostfreqgap=10 toplayer_minwidth=4 toplayer_maxwidth=5.2 toplayer_prefwidth=4 midlayer1_minwidth=4 midlayer1_maxwidth=5.2 midlayer1_prefwidth=4 midlayer2_minwidth=4 midlayer2_maxwidth=5.2 midlayer2_prefwidth=4 midlayer3_minwidth=4 midlayer3_maxwidth=5.2 midlayer3_prefwidth=4 midlayer4_minwidth=4 midlayer4_maxwidth=5.2 midlayer4_prefwidth=4 midlayer5_minwidth=4 midlayer5_maxwidth=5.2 midlayer5_prefwidth=4 midlayer6_minwidth=4 midlayer6_maxwidth=5.2 midlayer6_prefwidth=4 bottomlayer_minwidth=4 bottomlayer_maxwidth=5.2 bottomlayer_prefwidth=4 maxuncoupledlength=500
DiffPairsRouting [All] p2: maxlimit=7.2 minlimit=5 mostfreqgap=7.2 toplayer_maxgap=5 toplayer_prefgap=5 toplayer_minwidth=4 toplayer_maxwidth=5.2 toplayer_prefwidth=5.2 midlayer1_mingap=7.2 midlayer1_minwidth=4.8 midlayer1_maxwidth=4.8 midlayer1_prefwidth=4.8 midlayer2_mingap=7.2 midlayer2_minwidth=4.8 midlayer2_maxwidth=4.8 midlayer2_prefwidth=4.8 midlayer3_mingap=7.2 midlayer3_minwidth=4.8 midlayer3_maxwidth=4.8 midlayer3_prefwidth=4.8 midlayer4_mingap=7.2 midlayer4_minwidth=4.8 midlayer4_maxwidth=4.8 midlayer4_prefwidth=4.8 midlayer5_mingap=7.2 midlayer5_minwidth=4.8 midlayer5_maxwidth=4.8 midlayer5_prefwidth=4.8 midlayer6_mingap=7.2 midlayer6_minwidth=4.8 midlayer6_maxwidth=4.8 midlayer6_prefwidth=4.8 bottomlayer_maxgap=5 bottomlayer_prefgap=5 bottomlayer_minwidth=5.2 bottomlayer_maxwidth=5.2 bottomlayer_prefwidth=5.2 maxuncoupledlength=500
FabricationTestPointUsage TestPointUsage [All] p1: valid=2 allowmultiple=FALSE
FabricationTestpoint Testpoint [All] p1: side=3 testpointundercomponent=TRUE minsize=40 maxsize=100 preferedsize=60 minholesize=0 maxholesize=40 preferedholesize=32 testpointgrid=1 allowsidetop=TRUE allowsidebottom=TRUE usegrid=TRUE gridtolerance=0.01
FanoutControl Fanout_LCC [IsLCC] p1: bgadir=Out bgaviamode=Centered fanoutstyle=Auto fanoutdirection=Alternating viagrid=1 // Fanout_LCC (Default Rule)
FanoutControl Fanout_BGA [IsBGA] p2: bgadir=Out bgaviamode=Centered fanoutstyle=Auto fanoutdirection=Alternating viagrid=1 // Fanout_BGA (Default Rule)
FanoutControl Fanout_Default [All] p4: bgadir=Out bgaviamode=Centered fanoutstyle=Auto fanoutdirection=Alternating viagrid=1 // Fanout_Default (Default Rule)
FanoutControl Fanout_Small [(CompPinCount < 5)] p5: bgadir=Out bgaviamode=Centered fanoutstyle=Auto fanoutdirection=OutThenIn viagrid=1 // Fanout_Small (Default Rule)
Height Room_Hieght [WithinRoom('Room_Hieght 1 MM')] p1: minheight=0 maxheight=41.34 prefheight=39.37
HoleSize [All] p1: absolutevalues=TRUE maxlimit=280 minlimit=5.9 maxpercent=80.000 minpercent=20.000
HoleToHoleClearance HoleToHoleClearance_1 [InDrillLayerPair('Top Layer - L2_GND') vs InDrillLayerPair('Top Layer - L2_GND')] p1: gap=7.7 allowstackedmicrovias=TRUE
HoleToHoleClearance [All] p2: gap=8 allowstackedmicrovias=TRUE
MatchedLengths MatchedLengths_SPI [InxSignalClass('SPI')] p1: tolerance=2 checknetsindiffpair=FALSE checkdiffpairvsdiffpair=TRUE checkxsignals=TRUE checkothers=TRUE
MatchedLengths MatchedLengths-J2-J6 [InxSignalClass('J2-J6')] p2: tolerance=15 checknetsindiffpair=FALSE checkdiffpairvsdiffpair=TRUE checkxsignals=TRUE checkothers=TRUE
MatchedLengths MatchedLengths_U1-J6 [InxSignalClass('U1-J6')] p3: tolerance=15 checknetsindiffpair=FALSE checkdiffpairvsdiffpair=TRUE checkxsignals=TRUE checkothers=TRUE
MatchedLengths MatchedLengths-U1-J1 [InxSignalClass('U1-J1')] p4: tolerance=15 checknetsindiffpair=FALSE checkdiffpairvsdiffpair=TRUE checkxsignals=TRUE checkothers=TRUE
MatchedLengths MatchedLengths_Pairs [InxSignalClass('All xSignals')] p5: tolerance=10 checknetsindiffpair=TRUE checkdiffpairvsdiffpair=FALSE checkxsignals=FALSE checkothers=FALSE
MinimumAnnularRing MinimumAnnularRing_ThermalPadVias [IsVia and InAnyComponent] p1: minimumring=3.9
MinimumAnnularRing [All] p2: minimumring=3.9
MinimumSolderMaskSliver MinimumSolderMaskSliver_Logo [InComponentClass('Logo') vs InComponentClass('Logo')] p1: minsoldermaskwidth=0.7
MinimumSolderMaskSliver [All] p2: minsoldermaskwidth=3.5
PlaneConnect [All] p1: planeconnectstyle=Relief reliefexpansion=10 reliefentries=4 reliefconductorwidth=10 reliefairgap=10
PolygonConnect [All] p1: connectstyle=Direct reliefconductorwidth=10 reliefentries=4 polygonreliefangle="90 Angle" airgapwidth=10
RoomDefinition BGA1 [WithinRoom('BGA1')] p1: confinementstyle=ConfineIn formatcopy=TRUE lockcomponents=FALSE outline 830,2673.77 1999.28,2673.77 1999.28,1914.05 1921,1835.77 1921,1801.77 1663,1543.77 1415,1543.77 1414,1542.77 1414,1369.77 1477,1306.77 1477,1222.77 1467,1212.77 1435,1212.77 1418,1195.77 1362,1195.77 1362,1149.77 1345,1132.77 1266,1132.77 1256,1142.77 1256,1176.77 1224,1208.77 1190,1208.77 1177,1221.77 1177,1262.77 1084,1355.77 904,1355.77 839,1420.77 839,1566.77 807,1598.77 729,1598.77 711,1580.77 681,1580.77 674,1587.77 674,1680.77 678,1684.77 808,1684.77 844,1720.77 844,1917.77 830,1931.77
RoutingVias ThermalPadVias [IsVia and InAnyComponent] p1: holewidth=7.87 width=19.68 viastyle="Through Hole" minholewidth=5 minwidth=13 maxholewidth=12.99 maxwidth=23.62
RoutingVias [All] p2: holewidth=12.2 width=22.4 viastyle="Through Hole" minholewidth=5.9 minwidth=15.74 maxholewidth=20 maxwidth=40
SMDToCorner [All] p1: distance=25000
SilkToBoardRegionClearance [Not ((IsComment or IsDesignator) And (Hide <> 'False')) and not InRegion(1000,500,4000,800)] p1:
SilkToSilkClearance [All] p1: silktosilkclearance=3
SilkToSolderMaskClearance SilkToSolderMaskClearance_OutLine [istrack and InAnyComponent] p1: minsilkscreentomaskgap=0 clearancetoexposedcopper=FALSE
SilkToSolderMaskClearance SilkscreenOverComponentPads [IsPad] p2: minsilkscreentomaskgap=3 clearancetoexposedcopper=FALSE
SolderMaskExpansion [All] p1: expansion=0
Width [All] p1: maxlimit=100 minlimit=4 preferedwidth=6
13 further rules are at their usual default settings.

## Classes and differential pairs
net class LVDS: NetJ1_28 NetJ1_30 NetJ1_34 NetJ1_36 NetJ1_40 NetJ1_42 NetJ1_46 NetJ1_48 NetJ2_21 NetJ2_23 NetJ2_27 NetJ2_29 NetJ2_39 NetJ2_41 NetJ6_20 NetJ6_22 NetJ6_26 NetJ6_28 NetJ6_32 NetJ6_34 NetJ6_38 NetJ6_40 NetJ6_44 NetJ6_46 NetJ6_50 NetJ6_52 NetJ6_56 NetJ6_58 RADAR_LVDS_0M RADAR_LVDS_0P RADAR_LVDS_1M RADAR_LVDS_1P RADAR_LVDS_2M RADAR_LVDS_2P RADAR_LVDS_3M RADAR_LVDS_3P RADAR_LVDS_CLKM RADAR_LVDS_CLKP RADAR_LVDS_FRCLKM RADAR_LVDS_FRCLKP RADAR_LVDS_VALIDM RADAR_LVDS_VALIDP
net class 1A: CB_PMIC_1V0 CB_PMIC_1V2 CB_PMIC_1V8 PMIC_1V0 PMIC_1V2 PMIC_1V8 PMIC_3V3 RADAR_1P0_RF1 RADAR_1P0_RF2 RADAR_1V2 RADAR_1V8 RADAR_3V3 VCC_LD_SW_3V3
pad class "Mounting Holes PADS": Free-TH1 Free-TH2 Free-TH3 Free-TH4 Free-TH5 Free-TH6 Free-TH7 Free-TH8 Free-TH9
net class "Diff Pairs": NetJ1_28 NetJ1_30 NetJ1_34 NetJ1_36 NetJ1_40 NetJ1_42 NetJ1_46 NetJ1_48 RADAR_LVDS_0M RADAR_LVDS_0P RADAR_LVDS_1M RADAR_LVDS_1P RADAR_LVDS_CLKM RADAR_LVDS_CLKP RADAR_LVDS_FRCLKM RADAR_LVDS_FRCLKP
component class Logo: Logo1 Logo5
component class FiducialMark: FID1 FID2 FID3 FID4 FID5 FID6
component class Label: LBL1
component class PROC073C_Decoupling_caps: C1 C2 C3 C4 C5 C6 C7 C8 C9 C10 C11 C12 C13 C14 C15 C16 C17 C18 C19 C20 C21 C22 C23 C24 C25 C26 C27 C28 C29 C30 C64 C76 C77 C78 C79 C80 C81 C82 C83 L1 L2 L3 L7 R1
component class PROC073C_EVM_Hardware: "CAUTION HOT SURFACE1" FID1 FID2 FID3 FID4 FID5 FID6 LBL1 Logo1 Logo2 LOGO3 Logo4 Logo5 ZZ1 ZZ2 ZZ3 ZZ4 ZZ5
component class PROC073C_HD_Connector_60Pin: J1 J2 R4 R5 R6 R7 R8 R9 R10 R11 R12 R13 R15 R16 R17 R18 R19 R20 R21 R22 R23 R24 R26 R27 R28 R30 R31 R32 R33 R34 R35 R36 R37 R38 R39 R40 R41 R42 R52 R53 R58 R59 R60 R61 R62 R63 R64 R65 R66 R67 R124 R125 R126 R127 R128 R129 R130 R131 R132 R133 R134 R135 R136 R137 R140 TP14
component class PROC073C_IWR6843_Chip: C31 C32 C33 R72 R73 R74 R75 R76 R77 R150 R152 R153 R154 R155 R156 R169 TP2 TP3 TP4 TP5 TP6 TP7 U1 Y1
component class PROC073C_Can_Interface: C37 C38 C39 C40 C41 C42 C43 J3 J4 R3 R68 R69 R70 R71 R78 R79 R80 R81 R82 R83 R84 R85 R86 R87 R88 R89 R216 U5 U12 U13
component class PROC073C_QSPI_Flash_section: C34 C35 R43 R44 R45 R46 R47 R48 R49 R50 R51 U2
component class PROC073C_Temp_Current_sensor: C36 C57 C58 C59 C63 C65 R2 R14 R25 R29 R54 R55 R56 R57 R94 R101 R103 R104 R105 R106 R107 R108 R109 R110 R111 R112 R113 R114 R115 R116 R117 R139 R142 R143 R144 R145 R146 R147 R151 R157 R158 R159 R160 R161 R162 U3 U6 U7 U8 U10 U11
net class "TX and RX": RX1 RX2 RX3 RX4 TX1 TX2 TX3
component class AssemblyNote: ZZ1 ZZ2 ZZ3 ZZ4 ZZ5
net class Flash: RADAR_QSPI_CS RADAR_QSPI_D0 RADAR_QSPI_D1 RADAR_QSPI_D2 RADAR_QSPI_D3 RADAR_QSPI_SCLK
component class PROC073C_Flash_USB_To_UART: C44 C45 C46 C47 C48 C49 C50 C51 D1 D2 D4 FL1 FL2 J5 L9 L10 LD1 R90 R91 R92 R93 R95 R96 R97 R98 R99 R100 R102 R118 R119 R120 R121 TP1 TP8 U14 U15 U16
component class PROC073C_HD_DCA_Conn: C52 C53 D5 D7 J6 LD2 LD4 Q1 R122 R123 R138 R141 R148 R149 R163 R164 R165 R166 R167 R168 R170 R171 R212 R213 R214 R215 R217 R218 R219 R220 R221 R222 R223 R224 R225 R226 R227 R228 R229 R230 S2 S3 SW1 SW2 TP12 TP13 U17
component class PROC073C_PMIC: C54 C55 C56 C60 C61 C62 C66 C67 C68 C69 C70 C71 C72 C73 C74 C75 D3 D6 FL3 FL4 L4 L5 L6 L8 L11 L12 LD3 Q2 R172 R173 R174 R175 R176 R177 R178 R179 R180 R181 R182 R183 R184 R185 R186 R187 R188 R189 R190 R191 R192 R193 R194 R195 R196 R197 R198 R199 R200 R201 TP9 TP10 TP11 U4 U9
component class PROC073C_SOP_Ctrl: R202 R203 R204 R205 R206 R207 R208 R209 R210 R211 S1
differential pair NewDifferentialPair21: +NetJ6_38 -NetJ6_40
differential pair NewDifferentialPair20: +RADAR_LVDS_2P -RADAR_LVDS_2M
differential pair NewDifferentialPair19: +NetJ2_23 -NetJ2_21
differential pair NewDifferentialPair18: +NetJ6_32 -NetJ6_34
differential pair NewDifferentialPair17: +RADAR_LVDS_3P -RADAR_LVDS_3M
differential pair NewDifferentialPair16: +NetJ2_29 -NetJ2_27
differential pair NewDifferentialPair15: +NetJ2_41 -NetJ2_39
differential pair NewDifferentialPair14: +RADAR_LVDS_VALIDP -RADAR_LVDS_VALIDM
differential pair NewDifferentialPair13: +NetJ6_20 -NetJ6_22
differential pair NewDifferentialPair12: +NetJ6_28 -NetJ6_26
differential pair NewDifferentialPair11: +NetJ6_44 -NetJ6_46
differential pair NewDifferentialPair10: +NetJ6_52 -NetJ6_50
differential pair NewDifferentialPair9: +NetJ6_58 -NetJ6_56
differential pair NewDifferentialPair8: +NetJ1_30 -NetJ1_28
differential pair NewDifferentialPair7: +NetJ1_36 -NetJ1_34
differential pair NewDifferentialPair6: +NetJ1_42 -NetJ1_40
differential pair NewDifferentialPair5: +NetJ1_48 -NetJ1_46
differential pair NewDifferentialPair4: +RADAR_LVDS_FRCLKM -RADAR_LVDS_FRCLKP
differential pair NewDifferentialPair3: +RADAR_LVDS_CLKM -RADAR_LVDS_CLKP
differential pair NewDifferentialPair2: +RADAR_LVDS_1M -RADAR_LVDS_1P
differential pair NewDifferentialPair1: +RADAR_LVDS_0M -RADAR_LVDS_0P

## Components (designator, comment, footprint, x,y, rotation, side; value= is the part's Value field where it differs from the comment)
C1 "CGA5L1X7R0J226M160AC" 1206_180 1230.15,1083.72 r180 bottom value=22uF
C2 "CGA5L1X7R0J226M160AC" 1206_180 1021.11,2369.87 r270 bottom value=22uF
C3 "CGA5L1X7R0J226M160AC" 1206_180 882.8,2049.32 r90 bottom value=22uF
C4 "GCM155R71C224KE02D" 0402L 1374.59,1781.77 r270 top value=0.22uF
C5 "GCM155R71C224KE02D" 0402L 1419.18,1456.18 r180 top value=0.22uF
C6 "GCM155R71C224KE02D" 0402L 1325,1514.77 r180 bottom value=0.22uF
C7 "C0805C106M8RACTU" 0805_HV 1495.59,1784.77 r180 bottom value=10uF
C8 "C0805C106M8RACTU" 0805_HV 1495.59,1894.77 r180 bottom value=10uF
C9 "GCM155R71C224KE02D" 0402L 1200,1369.77 r90 bottom value=0.22uF
C10 "GCM155R71C224KE02D" 0402L 960.59,1574.77 r180 bottom value=0.22uF
C11 "GCM155R71C224KE02D" 0402L 1007.18,1761.18 r270 bottom value=0.22uF
C12 "GCM155R71C224KE02D" 0402L 1181.59,1733.77 r180 bottom value=0.22uF
C13 "C0805C106M8RACTU" 0805_HV 1183.59,1793.77 r180 bottom value=10uF
C14 "GCM155R71C224KE02D" 0402L 1505.59,1454.77 r180 top value=0.22uF
C15 "C0805C106M8RACTU" 0805_HV 1615,1449.77 r270 top value=10uF
C16 "GCM155R71C224KE02D" 0402L 1163.59,1224.77 r90 top value=0.22uF
C17 "GCM188R70J225KE22D" 0603 800.59,1584.77 r0 top value=2.2uF
C18 "GCM188R71C105KA64D" 0603 1436.78,1381.18 r180 top value=1uF
C19 "GCM155R71C224KE02D" 0402L 1049.18,1761.18 r270 bottom value=0.22uF
C20 "GCM155R71C224KE02D" 0402L 1346.59,1854.77 r180 bottom value=0.22uF
C21 "GCM155R71C224KE02D" 0402L 806.59,1535.77 r0 top value=0.22uF
C22 "GCM188R71C105KA64D" 0603 1440.59,1524.77 r180 top value=1uF
C23 "C0805C106M8RACTU" 0805_HV 1030.59,1879.77 r90 bottom value=10uF
C24 "C0805C106M8RACTU" 0805_HV 1345.59,1764.77 r180 bottom value=10uF
C25 "GCM155R71C104KA55D" 0402L 875.59,1314.77 r0 top value=0.1uF
C26 "GCM155R71C104KA55D" 0402L 1134.5,1300.77 r90 top value=0.1uF
C27 "GCM188R70J225KE22D" 0603 810.59,1364.77 r0 top value=2.2uF
C28 "GCM155R71C224KE02D" 0402L 850.59,1669.77 r0 top value=0.22uF
C29 "GCM155R71C224KE02D" 0402L 980.59,1514.77 r270 bottom value=0.22uF
C30 "GCM155R71E103KA37D" 0402L 1105,1324.77 r270 bottom value=0.01uF
C31 "GRM033C71A104KE14D" 0201#1 1049.59,1421.77 r90 bottom value=0.1uF
C32 "GJM1555C1H4R7BB01D" 0402L 1435.59,1274.77 r90 top value=4.7pF
C33 "GJM1555C1H4R7BB01D" 0402L 1315.59,1179.77 r180 top value=4.7pF
C34 "CGA2B3X7R1H104K050BB" 0402L 635.7,926.67 r180 top value=0.1uF
C35 "GCM188R71C105KA64D" 0603 647.51,860.63 r180 top value=1uF
C36 "CGA2B3X7R1H104K050BB" 0402L 900,954.77 r90 bottom value=0.1uF
C37 "C0402C104K8RACTU" 0402L 371.69,472.72 r90 bottom value=0.1uF
C38 "C0402C104K8RACTU" 0402L 265.63,589.74 r180 top value=0.1uF
C39 "GCM155R71H472KA37D" 0402L 179.95,450.74 r0 bottom value=4700pF
C40 "C0402C104K8RACTU" 0402L 293.22,255.44 r90 bottom value=0.1uF
C41 "C0402C104K8RACTU" 0402L 265.64,325.13 r180 bottom value=0.1uF
C42 "GCM155R71H472KA37D" 0402L 166.99,131.4 r0 bottom value=4700pF
C43 "C0402C104K8RACTU" 0402 682.22,726.76 r90 top value=0.1uF
C44 "GRM033R6YA104KE14D" "FP-GRM033R6YA104KE14D_0201 (0603 Metric)-IPC_C" 1886.12,301.92 r180 top
C45 "GRM033R6YA104KE14D" "FP-GRM033R6YA104KE14D_0201 (0603 Metric)-IPC_C" 1886.12,328.23 r180 top
C46 "CL05A106MP5NUNC" 0402_070 1789.78,82.28 r270 top value=10uF
C47 "CL05A106MP5NUNC" 0402_070 1828.84,82.28 r90 top value=10uF
C48 "GRM033R6YA104KE14D" "FP-GRM033R6YA104KE14D_0201 (0603 Metric)-IPC_C" 1882.6,543.11 r270 top
C49 "GRM033R6YA104KE14D" "FP-GRM033R6YA104KE14D_0201 (0603 Metric)-IPC_C" 1656.37,490.4 r270 top
C50 "GRM033R6YA104KE14D" "FP-GRM033R6YA104KE14D_0201 (0603 Metric)-IPC_C" 1610.54,622.77 r180 top
C51 "CL03A105MO3NRNH" FP-CL03A105MO3NRNH_0201-IPC_C 1704.92,566.28 r270 top
C52 "GRM033R6YA104KE14D" "FP-GRM033R6YA104KE14D_0201 (0603 Metric)-IPC_C" 639.02,1351.06 r0 top
C53 "GRM033R6YA104KE14D" "FP-GRM033R6YA104KE14D_0201 (0603 Metric)-IPC_C" 571.56,1307.45 r0 top
C54 "TMK063CG391JT-F" "FP-TMK063CG391JT-F_0201 (0603 Metric)-IPC_C" 854.8,481.54 r270 top
C55 "TMK063CG391JT-F" "FP-TMK063CG391JT-F_0201 (0603 Metric)-IPC_C" 1144.8,480.89 r270 top
C56 "TMK063CG391JT-F" "FP-TMK063CG391JT-F_0201 (0603 Metric)-IPC_C" 857.9,767.9 r270 top
C57 "CGA2B3X7R1H104K050BB" 0402L 1253.55,632.76 r180 top value=0.1uF
C58 "CGA2B3X7R1H104K050BB" 0402L 672.08,1973.74 r90 bottom value=0.1uF
C59 "CGA2B3X7R1H104K050BB" 0402L 810.31,940.08 r0 bottom value=0.1uF
C60 "TMK063CG391JT-F" "FP-TMK063CG391JT-F_0201 (0603 Metric)-IPC_C" 1139.71,770.25 r270 top
C61 "CL05A226MQ5N6J8" "FP-CL05A226MQ5N6J8_0402 (1005 Metric)-IPC_C" 984.51,413.06 r90 top
C62 "CL05A226MQ5N6J8" "FP-CL05A226MQ5N6J8_0402 (1005 Metric)-IPC_C" 1016.73,413.53 r90 top
C63 "CGA2B3X7R1H104K050BB" 0402L 898.74,1417.96 r180 bottom value=0.1uF
C64 "CGA5L1X7R0J226M160AC" 1206_180 554.85,2199.7 r0 bottom value=22uF
C65 "CGA2B3X7R1H104K050BB" 0402L 475,2434.77 r0 bottom value=0.1uF
C66 "CL05A226MQ5N6J8" "FP-CL05A226MQ5N6J8_0402 (1005 Metric)-IPC_C" 983.42,868.35 r270 top
C67 "CL05A226MQ5N6J8" "FP-CL05A226MQ5N6J8_0402 (1005 Metric)-IPC_C" 1015.86,868.35 r270 top
C68 "LMK063BJ224MP-F" 0201_033L 1112.94,634.48 r270 top value=0.22uF
C69 "CL10B105KQ8NNNC" 0603 763.67,1037.97 r270 top value=1uF
C70 "C0603C104J5RACTU" 0603 708.74,1344.77 r90 top value=0.1uF
C71 "CGA2B3X7S2A102K050BB" 0402 933.74,1224.77 r270 top value=1000pF
C72 "CL05A106MP5NUNC" 0402_070 1031.96,760.63 r180 top value=10uF
C73 "CL05A106MP5NUNC" 0402_070 1031.68,510.63 r180 top value=10uF
C74 "CL05A106MP5NUNC" 0402_070 969.08,760.63 r0 top value=10uF
C75 "CL05A106MP5NUNC" 0402_070 969.08,510.63 r0 top value=10uF
C76 "GCM32ER71C226KE19L" 1210_280 1380.16,2039.19 r0 bottom value=22uF
C77 "GCM21BR71A106KE22L" 0805_HV 1355.2,2148.45 r0 bottom value=10uF
C78 "GCM32ER71C226KE19L" 1210_280 1148.04,2157.85 r90 bottom value=22uF
C79 "GCM21BR71A106KE22L" 0805_HV 1034.97,2132.89 r90 bottom value=10uF
C80 "GCM32ER71C226KE19L" 1210_280 809.39,1895.19 r0 bottom value=22uF
C81 "GCM21BR71A106KE22L" 0805_HV 744.63,2195.15 r0 bottom value=10uF
C82 "GCM32ER71C226KE19L" 1210_280 1118.27,835.48 r0 bottom value=22uF
C83 "GCM21BR71A106KE22L" 0805_HV 1102.93,977.35 r0 bottom value=10uF
"CAUTION HOT SURFACE1" "CAUTION HOT SURFACE" IEC_HotSurface_Small 678.45,2381.29 r0 top
D1 "NSR20F30NXT5G" DSN2_0603 1927.08,61.77 r0 top value=30V
D2 "NSR20F30NXT5G" DSN2_0603 1756.62,604.69 r90 top value=30V
D3 "TLMY1000-GS08" TLMx1000_Yellow 650.96,457.8 r180 top value=Yellow
D4 "APHHS1005CGCK" APHHS1005_Green 1604.25,245.51 r270 top value=Green
D5 "APHHS1005CGCK" APHHS1005_Green 345.96,1420.88 r90 top value=Green
D6 "APHHS1005CGCK" APHHS1005_Green 1274.62,480.04 r180 top value=Green
D7 "APHHS1005CGCK" APHHS1005_Green 1875.31,1620.81 r0 top value=Green
FID1 "Fiducial" Fiducial10-20 294.16,2411.14 r90 top
FID2 "Fiducial" Fiducial10-20 2091.36,479.28 r90 bottom
FID3 "Fiducial" Fiducial10-20 70.7,298.59 r90 bottom
FID4 "Fiducial" Fiducial10-20 70.7,298.59 r90 top
FID5 "Fiducial" Fiducial10-20 294.16,2411.14 r90 bottom
FID6 "Fiducial" Fiducial10-20 2091.36,479.28 r90 top
J1 "QSH-030-01-L-D-A" Samtec_QSH-030-01-X-D-A 1708.74,1109.77 r0 bottom locked
J2 "QSH-030-01-L-D-A" Samtec_QSH-030-01-X-D-A 417.24,1109.77 r0 bottom locked
J3 "M50-3930342" FP-M50-3930342_HDR3-MFG 47.76,448.74 r270 top
J4 "M50-3930342" FP-M50-3930342_HDR3-MFG 47.76,131.4 r270 top
J5 "105017-0001" CONN_105017-0001 2055.12,201.38 r90 top
J6 "QSH-030-01-L-D-A" Samtec_QSH-030-01-X-D-A 1219.74,230.48 r270 bottom locked
L1 "MPZ2012S101A" MPZ2012 1087.23,1094.15 r270 bottom value="100 ohm"
L2 "MPZ2012S101A" MPZ2012 1171.01,2302.94 r0 bottom value="100 ohm"
L3 "MPZ2012S101A" MPZ2012 999.54,2008.62 r0 bottom value="100 ohm"
L4 "MCKK2012TR47M" "FP-MCKK2012TR47M_0805 (2012 Metric)-IPC_C" 935.96,434.56 r90 top
L5 "MCKK2012TR47M" "FP-MCKK2012TR47M_0805 (2012 Metric)-IPC_C" 1064.7,434.56 r90 top
L6 "MCKK2012TR47M" "FP-MCKK2012TR47M_0805 (2012 Metric)-IPC_C" 935.96,834.4 r270 top
L7 "MPZ2012S101A" MPZ2012 669.33,2114.23 r0 bottom value="100 ohm"
L8 "MCKK2012TR47M" "FP-MCKK2012TR47M_0805 (2012 Metric)-IPC_C" 1064.7,834.4 r270 top
L9 "BLM15PD300SZ1D" 0402L 1937.91,130.51 r270 top
L10 "BLM15PD300SZ1D" 0402L 1675.47,595.84 r90 top
L11 "BLM15PD300SZ1D" 0402L 1937.18,419.58 r0 top
L12 "BLM15PD300SZ1D" 0402L 863.92,409.21 r0 top
LBL1 "THT-14-423-10" Label_650x200 448.64,2105.95 r90 top
Logo1 "Texas Instruments" TI_Stacked_Overlay_Small 1726.87,1037.15 r0 top
Logo2 "CE Mark" CE_Mark_5mm 1000.93,515.95 r180 bottom
LOGO3 "FCC disclaimer" FCC_disclaimer 966.67,2489.6 r180 bottom (schematic designator Logo3)
Logo4 "WEEE logo" WEEE_Minimum 1836.06,549.11 r180 bottom
Logo5 "Texas Instruments" TI_Symbol_Overlay_Small 1337.21,2358.31 r180 bottom
Q1 "BSS123-7-F" FP-BSS123-7-F_SOT23-IPC_C 434.95,1438.6 r180 top
Q2 "BSS123" SOT-23 658.67,326 r180 top value=100V
R1 "MCT06030Z0000ZP500" 0603 1355.59,1939.77 r0 bottom value=0
R2 "CRCW040210K0FKED" 0402L 1215.81,813.9 r90 top value=10.0k
R3 "ERJ-2GE0R00X" 0402 350.51,392.41 r0 bottom value=0
R4 "CRCW02010000Z0ED" 0201_Silk 1424.97,923.97 r180 bottom value=0
R5 "CRCW02010000Z0ED" 0201_Silk 1425.43,810.89 r0 bottom value=0
R6 "CRCW02010000Z0ED" 0201_Silk 1425.43,880.18 r180 bottom value=0
R7 "CRCW02010000Z0ED" 0201_Silk 1614.76,935.2 r0 top value=0
R8 "CRCW02010000Z0ED" 0201_Silk 1425.43,845.53 r180 bottom value=0
R9 "CRCW02010000Z0ED" 0201_Silk 1443.74,958.34 r0 bottom value=0
R10 "CRCW02010000Z0ED" 0201_Silk 1844.67,950.58 r180 top value=0
R11 "CRCW02010000Z0ED" 0201_Silk 1614.76,975.28 r0 top value=0
R12 "CRCW02010000Z0ED" 0201_Silk 1614.76,1015.36 r180 top value=0
R13 "CRCW02010000Z0ED" 0201_Silk 1932.36,967.82 r0 bottom value=0
R14 "CRCW040210K0FKED" 0402L 1301.47,833.15 r270 bottom value=10.0k
R15 "CRCW020120R0FNED" 0201_033#1 1889.86,914.52 r0 top value=20.0
R16 "CRCW02010000Z0ED" 0201_Silk 1964.4,1109.48 r90 bottom value=0
R17 "CRCW020120R0FNED" 0201_033#1 1889.86,876.15 r0 top value=20.0
R18 "CRCW020120R0FNED" 0201_033#1 1614.76,1055.44 r0 top value=20.0
R19 "CRCW020120R0FNED" 0201_033#1 1448.74,1026.09 r0 bottom value=20.0
R20 "CRCW020120R0FNED" 0201_033#1 1383.28,1042.27 r0 bottom value=20.0
R21 "CRCW020120R0FNED" 0201_033#1 1614.76,1095.52 r0 top value=20.0
R22 "CRCW02010000Z0ED" 0201_Silk 1863.79,1052.42 r180 top value=0
R23 "CRCW020120R0FNED" 0201_033#1 1443.74,1062.27 r0 bottom value=20.0
R24 "CRCW02010000Z0ED" 0201_Silk 1863.79,1087.42 r180 top value=0
R25 "CRCW02010000Z0ED" 0201#2 1229.01,926.07 r90 top value=0
R26 "CRCW020120R0FNED" 0201_033#1 1443.74,1096.91 r0 bottom value=20.0
R27 "CRCW020120R0FNED" 0201_033#1 1448.74,1131.56 r0 bottom value=20.0
R28 "CRCW020120R0FNED" 0201_033#1 1448.74,1166.2 r0 bottom value=20.0
R29 "CRCW02010000Z0ED" 0201#2 1267.18,926.07 r90 top value=0
R30 "CRCW02010000Z0ED" 0201_Silk 1863.79,1136.89 r180 top value=0
R31 "CRCW02010000Z0ED" 0201_Silk 1932.36,1005.51 r0 bottom value=0
R32 "CRCW02010000Z0ED" 0201_Silk 1863.79,1171.89 r180 top value=0
R33 "CRCW02010000Z0ED" 0201_Silk 1863.79,1232.24 r180 top value=0
R34 "CRCW02010000Z0ED" 0201_Silk 1475,1421.77 r0 bottom value=0
R35 "CRCW02010000Z0ED" 0201_Silk 1863.79,1270.22 r180 top value=0
R36 "CRCW02010000Z0ED" 0201_Silk 1845.35,988.39 r180 top value=0
R37 "CRCW02010000Z0ED" 0201_Silk 1515,1455.77 r0 bottom value=0
R38 "CRCW02010000Z0ED" 0201_Silk 1725,1579.77 r180 bottom value=0
R39 "CRCW02010000Z0ED" 0201_Silk 1863.79,1334.43 r180 top value=0
R40 "CRCW02010000Z0ED" 0201_Silk 1725,1614.77 r180 bottom value=0
R41 "CRCW02010000Z0ED" 0201_Silk 1863.79,1372.41 r180 top value=0
R42 "CRCW02010000Z0ED" 0201_Silk 1932.38,930.27 r180 bottom value=0
R43 "ERJ-2GE0R00X" 0402 553.88,854.79 r270 top value=0
R44 "CRCW040210K0FKED" 0402L 418.88,1290.23 r90 top value=10.0k
R45 "CRCW020133R2FNED" 0201_Silk 403.88,847.19 r270 top value=33.2
R46 "CRCW020133R2FNED" 0201_Silk 503.88,1211.1 r270 top value=33.2
R47 "CRCW020133R2FNED" 0201_Silk 453.88,1211.1 r270 top value=33.2
R48 "CRCW020133R2FNED" 0201_Silk 453.88,847.19 r270 top value=33.2
R49 "CRCW040210K0FKED" 0402L 523.57,786.64 r0 top value=10.0k
R50 "CRCW040247K5FKED" 0402L 553.88,1212.19 r270 top value=47.5k
R51 "CRCW020133R2FNED" 0201_Silk 503.88,847.19 r270 top value=33.2
R52 "CRCW040210K0FKED" 0402L 809.93,980.11 r0 bottom value=10.0k
R53 "CRCW040210K0FKED" 0402L 768.74,1109.77 r90 bottom value=10.0k
R54 "CRCW040210K0FKED" 0402L 943.74,1139.77 r90 bottom value=10.0k
R55 "CRCW02010000Z0ED" 0201#2 839.48,1021.13 r0 bottom value=0
R56 "CRCW02010000Z0ED" 0201#2 843.74,1094.77 r0 bottom value=0
R57 "CRCW04020000Z0ED" 0402 990.93,896.1 r270 bottom value=0
R58 "CRCW02010000Z0ED" 0201_Silk 1931.3,1316.46 r0 bottom value=0
R59 "CRCW02010000Z0ED" 0201_Silk 1931.3,1354.7 r0 bottom value=0
R60 "CRCW02010000Z0ED" 0201_Silk 1448.74,1200.84 r180 bottom value=0
R61 "CRCW02010000Z0ED" 0201_Silk 1448.74,1235.48 r180 bottom value=0
R62 "CRCW02010000Z0ED" 0201_Silk 1448.74,1270.13 r180 bottom value=0
R63 "CRCW02010000Z0ED" 0201_Silk 1448.74,1304.77 r180 bottom value=0
R64 "CRCW02010000Z0ED" 0201_Silk 1475,1387.77 r180 bottom value=0
R65 "CRCW02010000Z0ED" 0201_Silk 1970,1559.77 r270 bottom value=0
R66 "CRCW02010000Z0ED" 0201_Silk 1935,1559.77 r90 bottom value=0
R67 "CRCW02010000Z0ED" 0201_Silk 1900,1559.77 r90 bottom value=0
R68 "CRCW040261R9FKED" 0402L 179.95,400.74 r180 bottom value=61.9
R69 "CRCW02010000Z0ED" 0201_Silk 371.69,544.66 r90 bottom value=0
R70 "CRCW040210K0FKED" 0402L 326.89,459.91 r270 bottom value=10.0k
R71 "CRCW040210K0FKED" 0402L 292.59,459.91 r90 bottom value=10.0k
R72 "ERJ-2GE0R00X" 0402 800.59,1949.77 r0 top value=0
R73 "ERJ-2GE0R00X" 0402 800.59,1904.77 r0 top value=0
R74 "ERJ-2GE0R00X" 0402 800.59,1814.77 r0 top value=0
R75 "ERJ-2GE0R00X" 0402 800.59,1859.77 r0 top value=0
R76 "ERJ-2GE0R00X" 0402 1490,1269.77 r90 top value=0
R77 "ERJ-2GE0R00X" 0402 1268.74,1129.77 r180 top value=0
R78 "ERJ-2GE0R00X" 0402 542.39,415.71 r270 bottom value=0
R79 "CRCW040261R9FKED" 0402L 179.95,500.74 r0 bottom value=61.9
R80 "ERJ-2GE0R00X" 0402 547.5,542.41 r180 top value=0
R81 "CRCW040261R9FKED" 0402L 166.99,81.4 r180 bottom value=61.9
R82 "CRCW02010000Z0ED" 0201_Silk 256.48,262.14 r270 bottom value=0
R83 "CRCW040210K0FKED" 0402L 549.57,180.17 r270 top value=10.0k
R84 "CRCW040210K0FKED" 0402L 587.71,180.16 r90 top value=10.0k
R85 "ERJ-2GE0R00X" 0402 469.06,180.13 r180 top value=0
R86 "CRCW040261R9FKED" 0402L 166.99,181.4 r0 bottom value=61.9
R87 "ERJ-2GE0R00X" 0402 469.06,325.13 r180 top value=0
R88 "CRCW040210K0FKED" 0402L 638.24,724.69 r90 top value=10.0k
R89 "CRCW04024K70JNED" 0402 755.42,695.23 r270 top value=4.7k
R90 "RC0201FR-074K99L" 0201L 1780.23,424.98 r270 top value=4.99k
R91 "RC0201JR-070RL" "FP-RC0201JR-070RL_0201 (0603 Metric)-MFG" 1945.7,209.97 r0 top
R92 "RC0201JR-070RL" "FP-RC0201JR-070RL_0201 (0603 Metric)-MFG" 1945.7,183.31 r0 top
R93 "RC0201FR-074K99L" 0201L 1702.37,418.68 r270 top value=4.99k
R94 "CRCW040210K0FKED" 0402L 1303.87,932.76 r270 top value=10.0k
R95 "RR0306P-103-D" FP-RR0306P-103-D_0201-IPC_C 1752.9,424.47 r270 top
R96 "RC0201JR-070RL" "FP-RC0201JR-070RL_0201 (0603 Metric)-MFG" 1693.49,145.26 r180 top
R97 "RC0201JR-070RL" "FP-RC0201JR-070RL_0201 (0603 Metric)-MFG" 1594.82,351.37 r180 top
R98 "RC0201JR-070RL" "FP-RC0201JR-070RL_0201 (0603 Metric)-MFG" 1594.82,322.25 r0 top
R99 "RC0201JR-07220RL" 0201L 1615.28,183.64 r180 top value=220
R100 "RR0306P-103-D" FP-RR0306P-103-D_0201-IPC_C 1912.81,668.16 r0 top
R101 "CRCW040210K0FKED" 0402L 1182.13,813.87 r270 top value=10.0k
R102 "RR0306P-103-D" FP-RR0306P-103-D_0201-IPC_C 1397.73,582.46 r0 top
R103 "CRCW040210K0FKED" 0402L 1266.47,833.15 r90 bottom value=10.0k
R104 "CRCW040210K0FKED" 0402L 378.85,1779.32 r180 bottom value=10.0k
R105 "CRCW040210K0FKED" 0402L 378.85,1742.89 r180 bottom value=10.0k
R106 "CRCW040210K0FKED" 0402L 634.64,726.36 r180 bottom value=10.0k
R107 "CRCW040210K0FKED" 0402L 674.01,645.31 r0 bottom value=10.0k
R108 "CRCW02010000Z0ED" 0201#2 542.98,2060.58 r90 bottom value=0
R109 "CRCW02010000Z0ED" 0201#2 715,1024.77 r0 bottom value=0
R110 "CRCW02010000Z0ED" 0201#2 577.98,2060.58 r90 bottom value=0
R111 "CRCW02010000Z0ED" 0201#2 715,989.77 r0 bottom value=0
R112 "CRCW040210K0FKED" 0402L 378.85,1961.46 r0 bottom value=10.0k
R113 "CRCW040210K0FKED" 0402L 378.85,1815.75 r0 bottom value=10.0k
R114 "CRCW040210K0FKED" 0402L 378.85,1706.46 r0 bottom value=10.0k
R115 "CRCW040210K0FKED" 0402L 636.16,1004.04 r270 bottom value=10.0k
R116 "CRCW040210K0FKED" 0402L 634.63,762.57 r0 bottom value=10.0k
R117 "CRCW040210K0FKED" 0402L 634.63,690.14 r0 bottom value=10.0k
R118 "RC0201JR-07510RL" 0201L 1555.79,634.76 r180 top value=510
R119 "CRCW0201100KFKED" 0201L 1467.08,593.51 r90 top value=100k
R120 "CRCW0201100KFKED" 0201L 1432.23,593.51 r270 top value=100k
R121 "CRCW0402200RFKEDHP" FP-CRCW0402200RFKEDHP_0402-IPC_C 1438.41,478.28 r0 top
R122 "ERJ-2GE0R00X" 0402L 729.49,260.83 r0 bottom value=0
R123 "RR0306P-103-D" FP-RR0306P-103-D_0201-IPC_C 622.73,1325.33 r180 top
R124 "CRCW020120R0FNED" 0201_033#1 658.74,1329.77 r180 bottom value=20.0
R125 "CRCW020120R0FNED" 0201_033#1 658.74,1294.77 r180 bottom value=20.0
R126 "CRCW020120R0FNED" 0201_033#1 643.74,1259.77 r180 bottom value=20.0
R127 "CRCW020120R0FNED" 0201_033#1 643.74,1224.77 r180 bottom value=20.0
R128 "CRCW020120R0FNED" 0201_033#1 643.74,1189.77 r180 bottom value=20.0
R129 "CRCW020120R0FNED" 0201_033#1 643.74,1159.77 r180 bottom value=20.0
R130 "CRCW020120R0FNED" 0201_033#1 643.74,1124.77 r180 bottom value=20.0
R131 "CRCW02010000Z0ED" 0201_Silk 260,1198.84 r0 top locked value=0
R132 "CRCW020120R0FNED" 0201_033#1 643.74,1089.77 r180 bottom value=20.0
R133 "CRCW02010000Z0ED" 0201_Silk 260,1163.84 r0 top locked value=0
R134 "CRCW02010000Z0ED" 0201_Silk 260,1113.02 r0 top locked value=0
R135 "CRCW02010000Z0ED" 0201_Silk 260,1078.02 r0 top locked value=0
R136 "CRCW02010000Z0ED" 0201_Silk 260,1004.77 r0 top locked value=0
R137 "CRCW02010000Z0ED" 0201_Silk 260,969.77 r0 top locked value=0
R138 "RR0306P-103-D" FP-RR0306P-103-D_0201-IPC_C 622.73,1373.63 r180 top
R139 "CRCW040210K0FKED" 0402L 960,1724.77 r90 bottom value=10.0k
R140 "CRCW02010000Z0ED" 0201_Silk 658.74,1364.77 r180 bottom value=0
R141 "RC0201JR-07510RL" 0201L 302.97,1414.19 r270 top value=510
R142 "CRCW040210K0FKED" 0402L 965,1644.77 r0 bottom value=10.0k
R143 "CRCW02010000Z0ED" 0201#2 888.74,1724.77 r90 bottom value=0
R144 "CRCW02010000Z0ED" 0201#2 833.74,1724.77 r90 bottom value=0
R145 "CRCW040210K0FKED" 0402L 798.74,1724.77 r270 bottom value=10.0k
R146 "CRCW040210K0FKED" 0402L 925,1724.77 r270 bottom value=10.0k
R147 "CRCW040210K0FKED" 0402L 965,1609.77 r180 bottom value=10.0k
R148 "CRCW020120R0FNED" 0201_033#2 1196.94,469.21 r270 bottom value=20.0
R149 "CRCW020120R0FNED" 0201_033#2 1234.31,469.21 r270 bottom value=20.0
R150 "CRCW040210K0JNED" 0402 1900,1427.68 r180 top value=10k
R151 "CRCW04020000Z0ED" 0402 977.93,1004.22 r270 bottom value=0
R152 "CRCW040210K0FKED" 0402L 1795.94,930.89 r90 top value=10.0k
R153 "CRCW0402100KFKED" 0402L 1840,1609.77 r0 bottom value=100k
R154 "CRCW0402100KFKED" 0402L 1840,1574.77 r0 bottom value=100k
R155 "CRCW0402100KFKED" 0402L 1717,952.94 r90 top value=100k
R156 "CRCW0402100KFKED" 0402L 1230,1284.77 r90 bottom value=100k
R157 "CRCW040210K0FKED" 0402L 475,2360.77 r180 bottom value=10.0k
R158 "CRCW040210K0FKED" 0402L 475,2394.77 r0 bottom value=10.0k
R159 "CRCW02010000Z0ED" 0201#2 429.59,2292.44 r180 bottom value=0
R160 "CRCW02010000Z0ED" 0201#2 429.59,2254.9 r180 bottom value=0
R161 "CRCW040210K0FKED" 0402L 870,2324.77 r0 bottom value=10.0k
R162 "CRCW040210K0FKED" 0402L 870,2289.77 r180 bottom value=10.0k
R163 "CRCW020120R0FNED" 0201_033#2 1271.67,469.21 r270 bottom value=20.0
R164 "CRCW020120R0FNED" 0201_033#2 1311.95,463.22 r270 bottom value=20.0
R165 "RR0306P-103-D" FP-RR0306P-103-D_0201-IPC_C 537.82,1296.93 r270 top
R166 "CRCW020120R0FNED" 0201_033#2 1352.68,463.22 r270 bottom value=20.0
R167 "CRCW020120R0FNED" 0201_033#2 1390.77,452.37 r270 bottom value=20.0
R168 "CRCW020120R0FNED" 0201_033#2 1429.92,452.37 r270 bottom value=20.0
R169 "CRCW040210K0JNED" 0402 1900,1499.77 r180 top value=10k
R170 "CRCW020120R0FNED" 0201_033#2 1467.83,452.37 r270 bottom value=20.0
R171 "RC0201JR-07510RL" 0201L 526.8,1391.99 r180 top value=510
R172 "ERJ-2GEJ511X" 0402L 659.82,406.64 r180 top value=510
R173 "RC0402FR-073R83L" "FP-RC0402FR-073R83L_0402 (1005 Metric)-IPC_C" 884.8,476.65 r270 top
R174 "RC0201JR-07510RL" 0201L 1281.31,528.75 r0 top value=510
R175 "RC0402FR-073R83L" "FP-RC0402FR-073R83L_0402 (1005 Metric)-IPC_C" 1118.8,476.93 r270 top
R176 "RC0201FR-074K99L" 0201L 1123.96,592.5 r0 top value=4.99k
R177 "RC0201FR-074K99L" 0201L 1124.8,676.01 r0 top value=4.99k
R178 "RC0402FR-073R83L" "FP-RC0402FR-073R83L_0402 (1005 Metric)-IPC_C" 872.8,807.65 r0 top
R179 "ERJ-2GEJ511X" 0402L 776.61,288.6 r180 top value=510
R180 "RC0201JR-070RL" "FP-RC0201JR-070RL_0201 (0603 Metric)-MFG" 878.14,597.5 r0 top
R181 "RC0201JR-070RL" "FP-RC0201JR-070RL_0201 (0603 Metric)-MFG" 877.8,622 r0 top
R182 "CRCW0402100KFKED" 0402L 776.6,323.18 r0 top value=100k
R183 "RC0402FR-073R83L" "FP-RC0402FR-073R83L_0402 (1005 Metric)-IPC_C" 1124.8,807.79 r180 top
R184 "CRCW040210K0JNED" 0402 1303.12,1292.36 r180 bottom value=10k
R185 "CRCW04020000Z0ED" 0402 1303.12,1344.13 r180 bottom value=0
R186 "RC0201JR-071KL" 0201L 1270.29,570.95 r270 top value=1.0k
R187 "RC0201FR-074K99L" 0201L 1124.8,704.35 r0 top value=4.99k
R188 "RC0201FR-074K99L" 0201L 874.94,574.5 r180 top value=4.99k
R189 "RR0306P-103-D" FP-RR0306P-103-D_0201-IPC_C 1124.42,562 r0 top
R190 "RR0306P-103-D" FP-RR0306P-103-D_0201-IPC_C 891.97,694.21 r90 top
R191 "RCS06030000Z0EA" 0603 738.67,1187.92 r90 top value=0
R192 "PMR18EZPFV2L00" 1206 1417.66,783.38 r90 top value=0.002
R193 "PMR18EZPFV2L00" 1206 794.24,680.61 r270 bottom value=0.002
R194 "RC0201FR-071K96L" 0201L 1239.41,570.95 r90 top value=1.96k
R195 "MCT06030Z0000ZP500" 0603 925.25,1065.92 r180 top value=0
R196 "CRCW0402510RJNED" 0402 932.6,1004.37 r180 top value=510
R197 "ERJ-2RKF1003X" 0402 848.74,1139.77 r0 bottom value=100k
R198 "RC0201JR-070RL" "FP-RC0201JR-070RL_0201 (0603 Metric)-MFG" 796.29,407.65 r90 top
R199 "PMR18EZPFV2L00" 1206 552.07,1798.74 r180 bottom value=0.002
R200 "PMR18EZPFV2L00" 1206 884.81,1270.12 r0 bottom value=0.002
R201 "CRCW0201100KFKED" 0201L 785.2,363.4 r0 top value=100k
R202 "ERJ-2GE0R00X" 0402L 911.88,64.04 r180 top value=0
R203 "CRCW040210K0FKED" 0402L 1002.05,77.62 r0 top value=10.0k
R204 "CRCW04027K87FKED" 0402L 1155.97,85.15 r0 top value=7.87k
R205 "CRCW040282K5FKED" 0402L 1002.05,43.89 r0 top value=82.5k
R206 "CRCW040210K0FKED" 0402L 920.56,118.98 r270 top value=10.0k
R207 "CRCW04027K87FKED" 0402L 1155.97,119.47 r0 top value=7.87k
R208 "CRCW040282K5FKED" 0402L 886.26,118.98 r270 top value=82.5k
R209 "CRCW040210K0FKED" 0402L 1002.05,155.42 r0 top value=10.0k
R210 "CRCW04027K87FKED" 0402L 1155.97,154.42 r0 top value=7.87k
R211 "CRCW040282K5FKED" 0402L 1002.05,120.94 r0 top value=82.5k
R212 "RC0201JR-07220RL" 0201L 1882,1576.82 r180 top value=220
R213 "RC0201JR-07220RL" 0201L 477.94,1661.26 r90 top value=220
R214 "RC0201JR-070RL" "FP-RC0201JR-070RL_0201 (0603 Metric)-IPC_C" 321.89,1486.65 r180 top
R215 "RR0306P-103-D" FP-RR0306P-103-D_0201-IPC_C 321.39,1516.38 r0 top
R216 "ERJ-2GE0R00X" 0402 635.54,184.1 r90 top value=0
R217 "CRCW02010000Z0ED" 0201_Silk 326.6,1198.84 r180 top locked value=0
R218 "CRCW02010000Z0ED" 0201_Silk 326.6,1163.84 r180 top locked value=0
R219 "CRCW02010000Z0ED" 0201_Silk 1797.27,1044.56 r0 top value=0
R220 "CRCW02010000Z0ED" 0201_Silk 1796.85,1095.72 r0 top value=0
R221 "CRCW02010000Z0ED" 0201_Silk 326.6,1113.02 r180 top locked value=0
R222 "CRCW02010000Z0ED" 0201_Silk 326.6,1078.02 r180 top locked value=0
R223 "CRCW02010000Z0ED" 0201_Silk 326.6,1004.77 r180 top locked value=0
R224 "CRCW02010000Z0ED" 0201_Silk 326.6,969.77 r180 top locked value=0
R225 "CRCW02010000Z0ED" 0201_Silk 1797.27,1129.03 r0 top value=0
R226 "CRCW02010000Z0ED" 0201_Silk 1796.85,1180.18 r0 top value=0
R227 "CRCW02010000Z0ED" 0201_Silk 1797.27,1224.38 r0 top value=0
R228 "CRCW02010000Z0ED" 0201_Silk 1796.85,1278.52 r0 top value=0
R229 "CRCW02010000Z0ED" 0201_Silk 1796.85,1326.22 r0 top value=0
R230 "CRCW02010000Z0ED" 0201_Silk 1796.85,1380.71 r0 top value=0
S1 "218-6LPST" SW_218-6LPST 1394.21,235.15 r90 top locked
S2 "B3U-1000P" SW_B3U-1000P 287.11,807.23 r0 top
S3 "B3U-1000P" SW_B3U-1000P 398.63,1583.31 r90 top
TP1 "TESTPOINT" TP_25MIL-SMT 1836.32,134.9 r270 top
TP2 "TP_SM_1MM" TP_SM_1MM 672.85,1987.78 r90 top
TP3 "TP_SM_1MM" TP_SM_1MM 643.74,1933.67 r90 top
TP4 "TP_SM_1MM" TP_SM_1MM 716.44,1814.77 r90 top
TP5 "TP_SM_1MM" TP_SM_1MM 629.51,1875.39 r90 top
TP6 "TP_SM_1MM" TP_SM_1MM 1552,1289.77 r90 top
TP7 "TP_SM_1MM" TP_SM_1MM 1450,1194.77 r90 top
TP8 "TESTPOINT" TP_25MIL-SMT 1510.32,634.76 r90 top
TP9 "TESTPOINT" TP_25MIL-SMT 2015.61,419.58 r0 top
TP10 "TESTPOINT" TP_25MIL-SMT 1867.15,419.58 r0 top
TP11 "TESTPOINT" TP_VIA_060RND040 478.18,237.78 r180 top
TP12 "5001" Keystone5001 618.57,64.04 r0 top
TP13 "5001" Keystone5001 750.27,64.04 r0 top
TP14 "5001" Keystone5001 394.54,635.9 r0 top
U1 "IWR6843QAGABL" ABL0161B 1125.98,1589.39 r270 top
U2 "MX25V1635FZNQ" WSON-8L_6x5MM_EP 478.88,1037.19 r270 top
U3 "TMP112AQDRLRQ1" DRL0006A 915.74,1049.77 r270 bottom
U4 "LP87524JRNFRQ1" RNF0026C 1000.33,634.48 r0 top
U5 "TCAN1042HGVDQ1" D0008A_L 349.29,467.41 r180 top
U6 "INA226AIDGST" DGS0010A_L 1303.36,766.27 r270 top
U7 "INA226AIDGST" DGS0010A_L 542.07,1923.74 r0 bottom
U8 "INA226AIDGST" DGS0010A_L 725.86,859.9 r0 bottom
U9 "TPS22917DBVR" DBV0006A_N 838.74,1189.77 r90 top
U10 "INA226AIDGST" DGS0010A_L 810.59,1549.77 r270 bottom
U11 "CAT24C08WI-GT3" SOIC-8 675,2349.77 r180 bottom
U12 "TCAN1042HGVDQ1" D0008A_L 272.44,250.13 r180 top
U13 "TS3A5018RSVR" RSV0016A 662.79,596.95 r0 top
U14 "CP2105-F01-GMR" FP-CP2105-F01-GMR_QFN24-EP-IPC_A 1735.81,273.04 r180 top
U15 "TS5A23157RSER" RSE0010A 1872.76,609.98 r270 top
U16 "TPS2115ADRBR" DRB0008B 1565.44,535.87 r0 top
U17 "SN74LVC1G11DSFR" DSF0006A 553.57,1349.48 r180 top
Y1 "CX3225SA40000D0PTWCC" Kyocera_CX3225SA 1335.59,1264.77 r90 top
ZZ1 "This Assembly Note is for PCB labels only" AssemblyNoteLabel -833.57,3597.27 r0 top
ZZ2 "These assemblies are ESD sensitive, ESD precautions shall be observed." AssemblyNote -831.16,3520.11 r0 top
ZZ3 "These assemblies must be clean and free from flux and all contaminants. Use of no clean flux is not acceptable." AssemblyNote -831.16,3433.3 r0 top
ZZ4 "These assemblies must comply with workmanship standards IPC-A-610 Class 2, unless otherwise specified." AssemblyNote -835.98,3341.67 r0 top
ZZ5 "INDICATION FOR COMPONENTS D* ARE GIVEN AT THEIR CATHODE SIDE." AssemblyNote -834.59,3254.07 r0 top

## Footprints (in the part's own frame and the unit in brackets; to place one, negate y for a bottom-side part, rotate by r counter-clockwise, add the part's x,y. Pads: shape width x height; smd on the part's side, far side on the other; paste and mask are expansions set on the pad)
0201#1 [mm] "Data from Kemet datasheet CC101_COM dated 7/28/11"
  rect 0.46x0.42 smd mask+0.048: 1(-0.33,0) 2(0.33,0)
  body extent -0.31,-0.16 0.31,0.16, height 0.26
0201#2 [mm] "Data from Kemet datasheet CC101_COM dated 7/28/11"
  rect 0.46x0.42 smd mask+0: 1(-0.33,0) 2(0.33,0)
  body extent -0.31,-0.16 0.31,0.16, height 0.26
0201_033#1 [mm] "SMD, 2-Leads, Height 0.33mm"
  rect 0.46x0.42 smd mask+0: 1(-0.33,0) 2(0.33,0)
  body extent -0.31,-0.16 0.31,0.16, height 0.33
0201_033#2 [mm] "SMD, 2-Leads, Height 0.33mm"
  rect 0.46x0.42 smd mask+0.048: 1(-0.33,0) 2(0.33,0)
  body extent -0.31,-0.16 0.31,0.16, height 0.33
0201_033L [mm] "0201"
  rect 0.36x0.32 smd mask+0.048: 1(-0.28,0) 2(0.28,0)
  body extent -0.31,-0.16 0.31,0.16, height 0.33
0201_Silk [mm] "Data from Kemet datasheet CC101_COM dated 7/28/11"
  rect 0.46x0.42 smd mask+0: 1(-0.33,0) 2(0.33,0)
  silkscreen extent -0.75,-0.4 0.75,0.4, body extent -0.31,-0.16 0.31,0.16, height 0.26
0201L [mm] "Data from Kemet datasheet CC101_COM dated 7/28/11"
  rect 0.36x0.32 smd mask+0.048: 1(-0.28,0) 2(0.28,0)
  body extent -0.31,-0.16 0.31,0.16, height 0.26
0402 [mm] "0402 from SM-752 data"
  rect 0.8x0.6 smd: 1(-0.6,0) 2(0.6,0)
  silkscreen extent -1.22,-0.52 1.22,0.52, body extent -0.55,-0.3 0.55,0.3, height 0.6
0402_070 [mil] "SMD, 2-Leads, Body 1.2x0.7mm, Height 0.7mm"
  rect 15x24 smd: 1(-20,0) 2(20,0)
  body extent -24,-14 24,14, height 28
0402L [mm] "0402 from SM-752 data"
  rect 0.6x0.5 smd: 1(-0.5,0) 2(0.5,0)
  body extent -0.55,-0.3 0.55,0.3, height 0.6
0603 [mm] "0603 from SM-752 data"
  rect 1x0.95 smd: 1(-0.8,0) 2(0.8,0)
  silkscreen extent -1.52,-0.69 1.52,0.69, body extent -0.87,-0.47 0.87,0.47, height 1
0805_HV [mil] "0805 with 30mil clearance between pads"
  rect 50x63 smd: 1(-40,0) 2(40,0)
  silkscreen extent -74,-40 74,40, body extent -43,-29 43,29, height 57
1206 [mm] "1206 from SM-752 data"
  rect 1.3x1.85 smd: 1(-1.45,0) 2(1.45,0)
  silkscreen extent -2.4,-1.21 2.4,1.21, body extent -1.7,-0.9 1.7,0.9, height 1.35
1206_180 [mm] "1206_180"
  rect 1.1x1.6 smd: 1(-1.7,0) 2(1.7,0)
  silkscreen extent -0.9,-1 0.9,1, body extent -1.75,-0.95 1.75,0.95, height 1.8
1210_280 [mm] "SMD, 2-Leads, Body 3.6x2.8mm, Height 2.8mm"
  rect 1.1x2.2 smd: 1(-1.65,0) 2(1.65,0)
  silkscreen extent -0.84,-1.4 0.84,1.4, body extent -1.8,-1.4 1.8,1.4, height 2.8
ABL0161B [mm] "BGA, 161-Balls, Body 10.4x10.4mm, Pitch 0.65mm"
  round 0.32 smd: A1(-4.55,4.55) A2(-3.9,4.55) A3(-3.25,4.55) A5(-1.95,4.55) A7(-0.65,4.55) A9(0.65,4.55) A10(1.3,4.55) A13(3.25,4.55) A14(3.9,4.55) A15(4.55,4.55) B1(-4.55,3.9) B2(-3.9,3.9) B3(-3.25,3.9) B4(-2.6,3.9) B5(-1.95,3.9) B6(-1.3,3.9) B7(-0.65,3.9) B8(0,3.9) B9(0.65,3.9) B10(1.3,3.9) B11(1.95,3.9) B12(2.6,3.9) B13(3.25,3.9) B14(3.9,3.9) B15(4.55,3.9) C1(-4.55,3.25) C2(-3.9,3.25) C3(-3.25,3.25) C4(-2.6,3.25) C5(-1.95,3.25) C6(-1.3,3.25) C7(-0.65,3.25) C8(0,3.25) C9(0.65,3.25) C13(3.25,3.25) C14(3.9,3.25) C15(4.55,3.25) D2(-3.9,2.6) D13(3.25,2.6) D14(3.9,2.6) D15(4.55,2.6) E1(-4.55,1.95) E2(-3.9,1.95) E3(-3.25,1.95) E5(-1.95,1.95) E6(-1.3,1.95) E8(0,1.95) E10(1.3,1.95) E11(1.95,1.95) E13(3.25,1.95) E14(3.9,1.95) E15(4.55,1.95) F2(-3.9,1.3) F3(-3.25,1.3) F5(-1.95,1.3) F9(0.65,1.3) F11(1.95,1.3) F13(3.25,1.3) F14(3.9,1.3) F15(4.55,1.3) G1(-4.55,0.65) G2(-3.9,0.65) G3(-3.25,0.65) G5(-1.95,0.65) G6(-1.3,0.65) G7(-0.65,0.65) G8(0,0.65) G10(1.3,0.65) G13(3.25,0.65) G14(3.9,0.65) G15(4.55,0.65) H2(-3.9,0) H3(-3.25,0) H5(-1.95,0) H7(-0.65,0) H9(0.65,0) H11(1.95,0) H13(3.25,0) H14(3.9,0) H15(4.55,0) J1(-4.55,-0.65) J2(-3.9,-0.65) J3(-3.25,-0.65) J5(-1.95,-0.65) J6(-1.3,-0.65) J7(-0.65,-0.65) J8(0,-0.65) J10(1.3,-0.65) J13(3.25,-0.65) J14(3.9,-0.65) J15(4.55,-0.65) K2(-3.9,-1.3) K3(-3.25,-1.3) K5(-1.95,-1.3) K7(-0.65,-1.3) K8(0,-1.3) K9(0.65,-1.3) K10(1.3,-1.3) K11(1.95,-1.3) K13(3.25,-1.3) K14(3.9,-1.3) K15(4.55,-1.3) L1(-4.55,-1.95) L2(-3.9,-1.95) L3(-3.25,-1.95) L5(-1.95,-1.95) L6(-1.3,-1.95) L8(0,-1.95) L10(1.3,-1.95) L13(3.25,-1.95) L14(3.9,-1.95) L15(4.55,-1.95) M2(-3.9,-2.6) M3(-3.25,-2.6) M14(3.9,-2.6) M15(4.55,-2.6) N1(-4.55,-3.25) N2(-3.9,-3.25) N3(-3.25,-3.25) N4(-2.6,-3.25) N5(-1.95,-3.25) N6(-1.3,-3.25) N7(-0.65,-3.25) N8(0,-3.25) N9(0.65,-3.25) N10(1.3,-3.25) N11(1.95,-3.25) N12(2.6,-3.25) N13(3.25,-3.25) N14(3.9,-3.25) N15(4.55,-3.25) P1(-4.55,-3.9) P2(-3.9,-3.9) P3(-3.25,-3.9) P4(-2.6,-3.9) P5(-1.95,-3.9) P6(-1.3,-3.9) P7(-0.65,-3.9) P8(0,-3.9) P9(0.65,-3.9) P10(1.3,-3.9) P11(1.95,-3.9) P12(2.6,-3.9) P13(3.25,-3.9) P14(3.9,-3.9) P15(4.55,-3.9) R1(-4.55,-4.55) R2(-3.9,-4.55) R3(-3.25,-4.55) R4(-2.6,-4.55) R5(-1.95,-4.55) R6(-1.3,-4.55) R7(-0.65,-4.55) R8(0,-4.55) R9(0.65,-4.55) R10(1.3,-4.55) R11(1.95,-4.55) R12(2.6,-4.55) R13(3.25,-4.55) R14(3.9,-4.55) R15(4.55,-4.55)
  silkscreen extent -5.3,-5.3 5.3,5.3, body extent -5.2,-5.2 5.2,5.2, height 0.62
APHHS1005_Green [mm] "SMD, 2-Leads, Body 1x0.5mm"
  rrect20% 0.7x0.5 smd: 1(-0.45,0) 2(0.45,0)
  silkscreen extent -0.8,-0.65 1.2,0.65, body extent -0.5,-0.25 0.5,0.25, height 0.5
AssemblyNote [mil] "Assembly Note"
AssemblyNoteLabel [mil] "Assembly Note for PCB Labels"
CE_Mark_5mm [mil] "Minimum text height for CE Mark"
  silkscreen extent -138,-98 138,98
